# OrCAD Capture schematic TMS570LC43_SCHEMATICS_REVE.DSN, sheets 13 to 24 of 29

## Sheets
13 PAGE27: Power Input: size B; note: Power Input
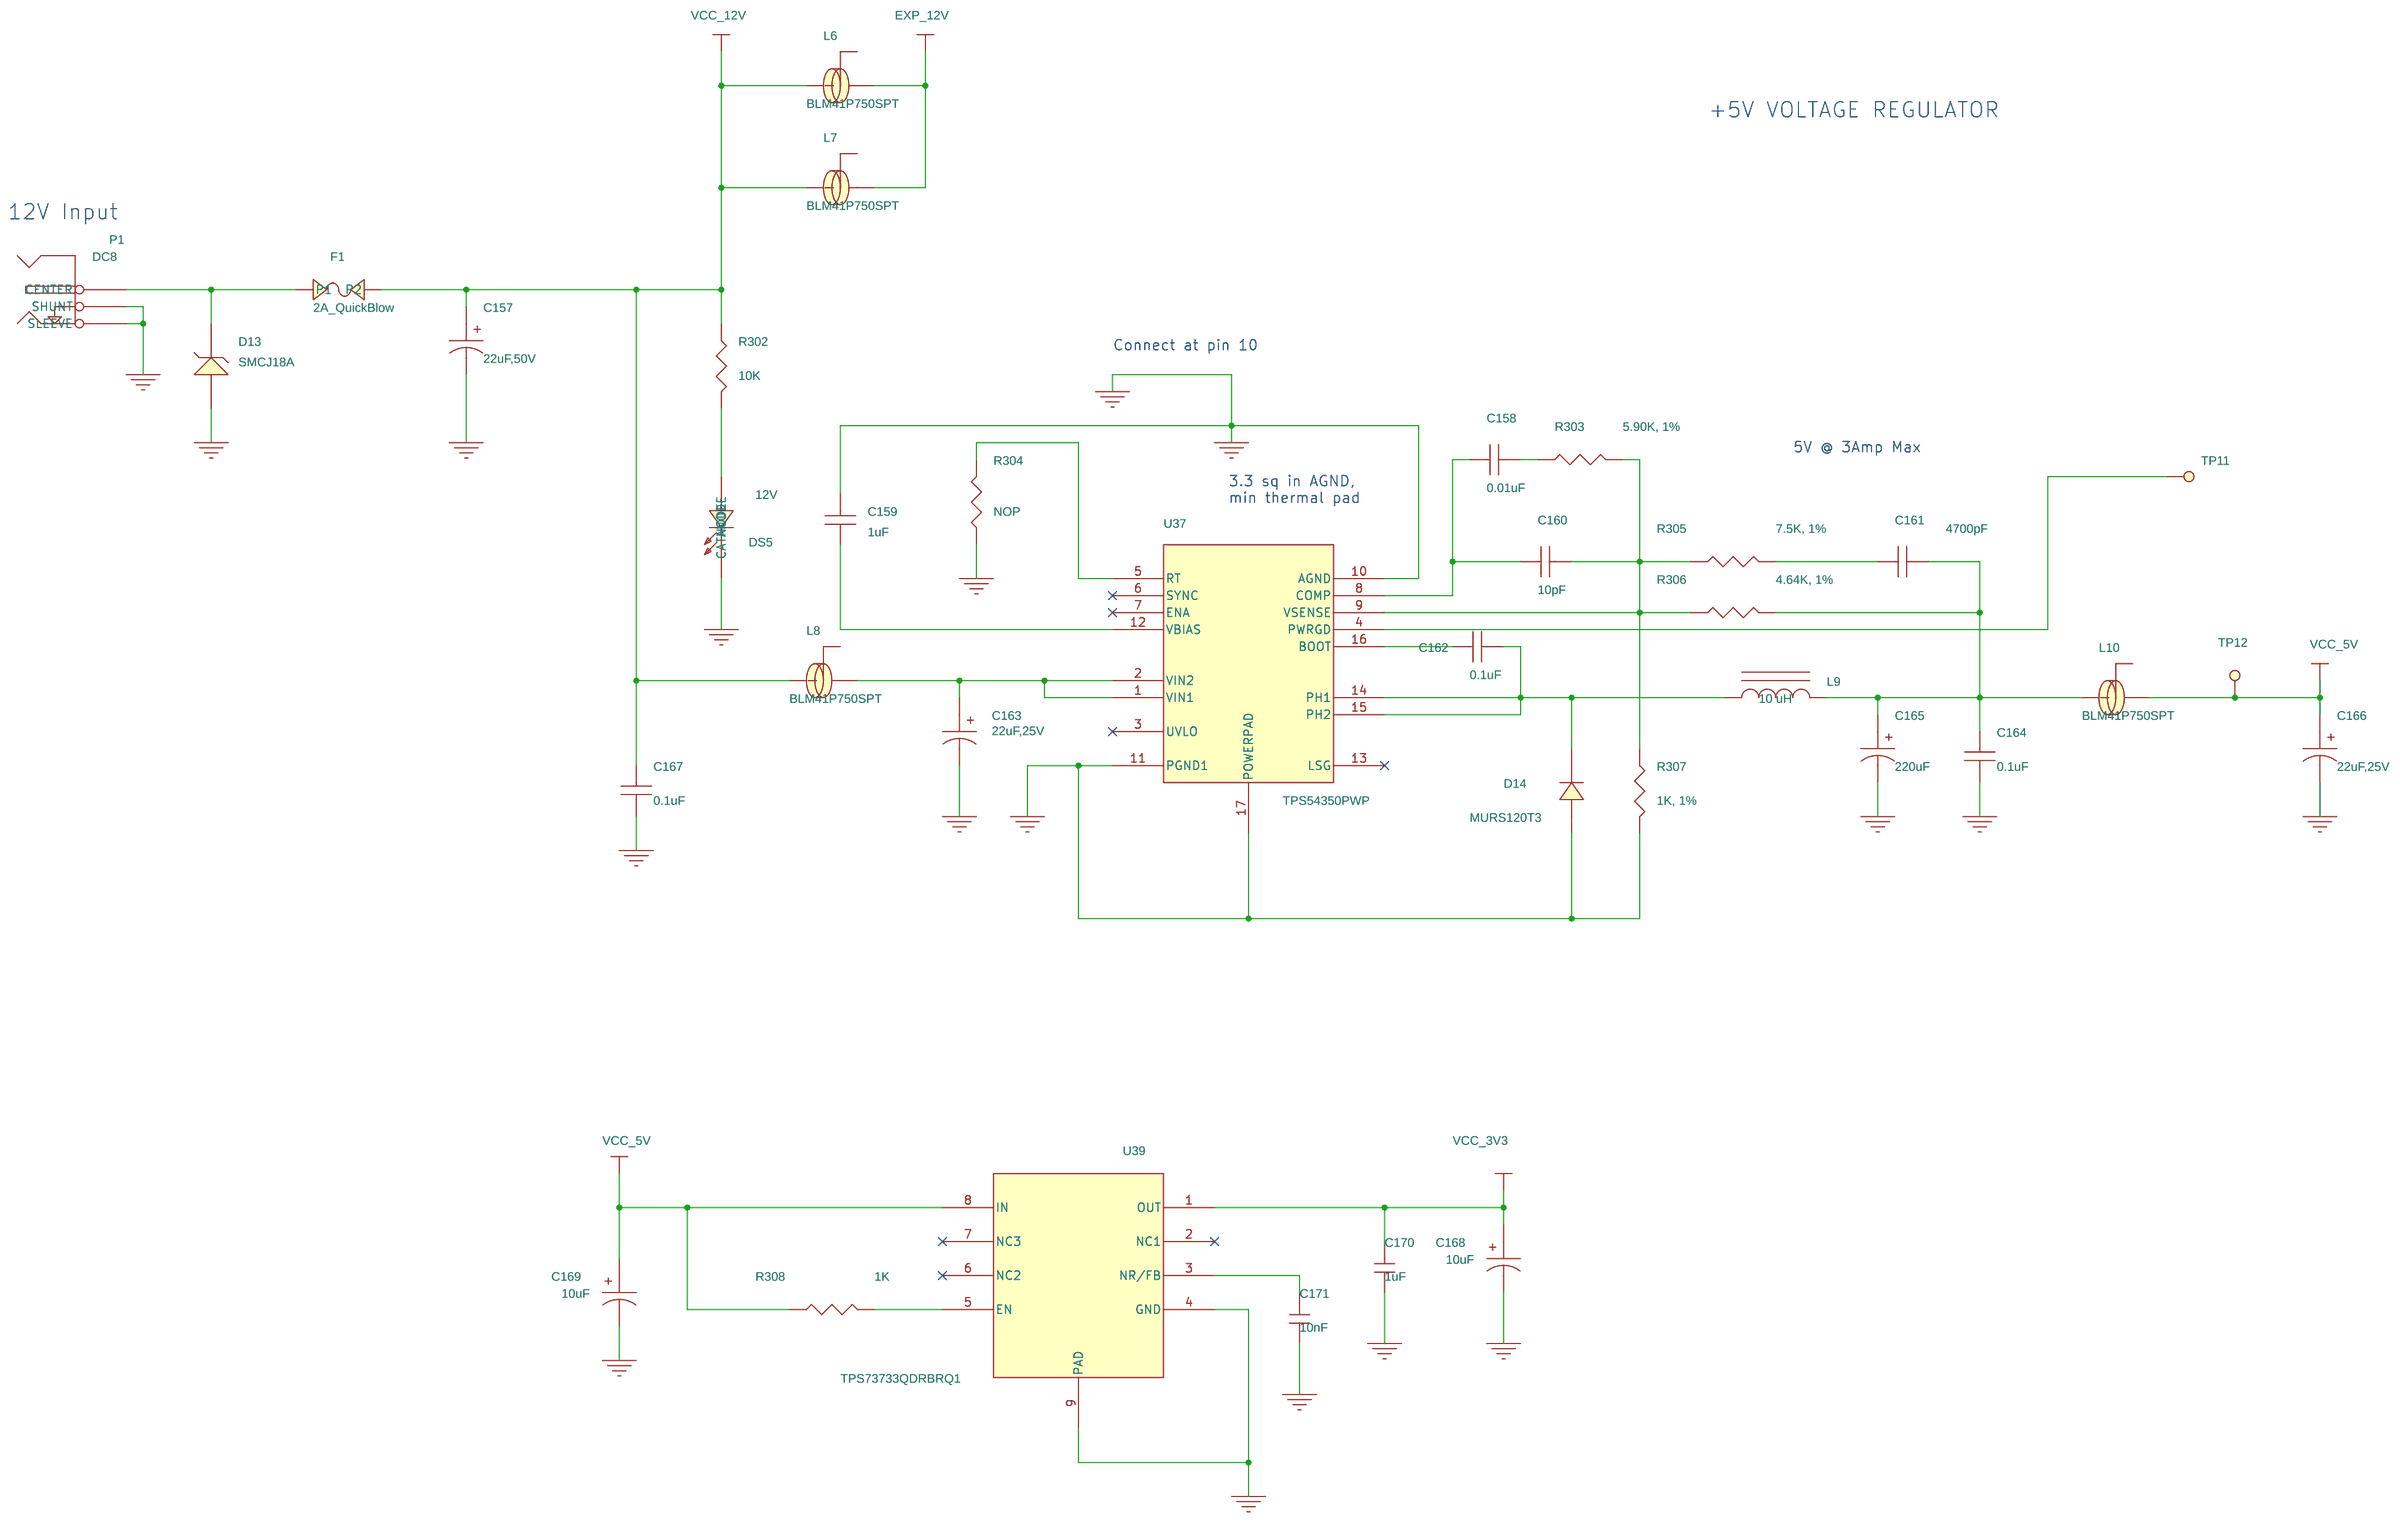
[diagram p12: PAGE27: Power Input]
14 PAGE07: MCU JTAG & OSC: size B; rev: D; note: MCU JTAG & OSC
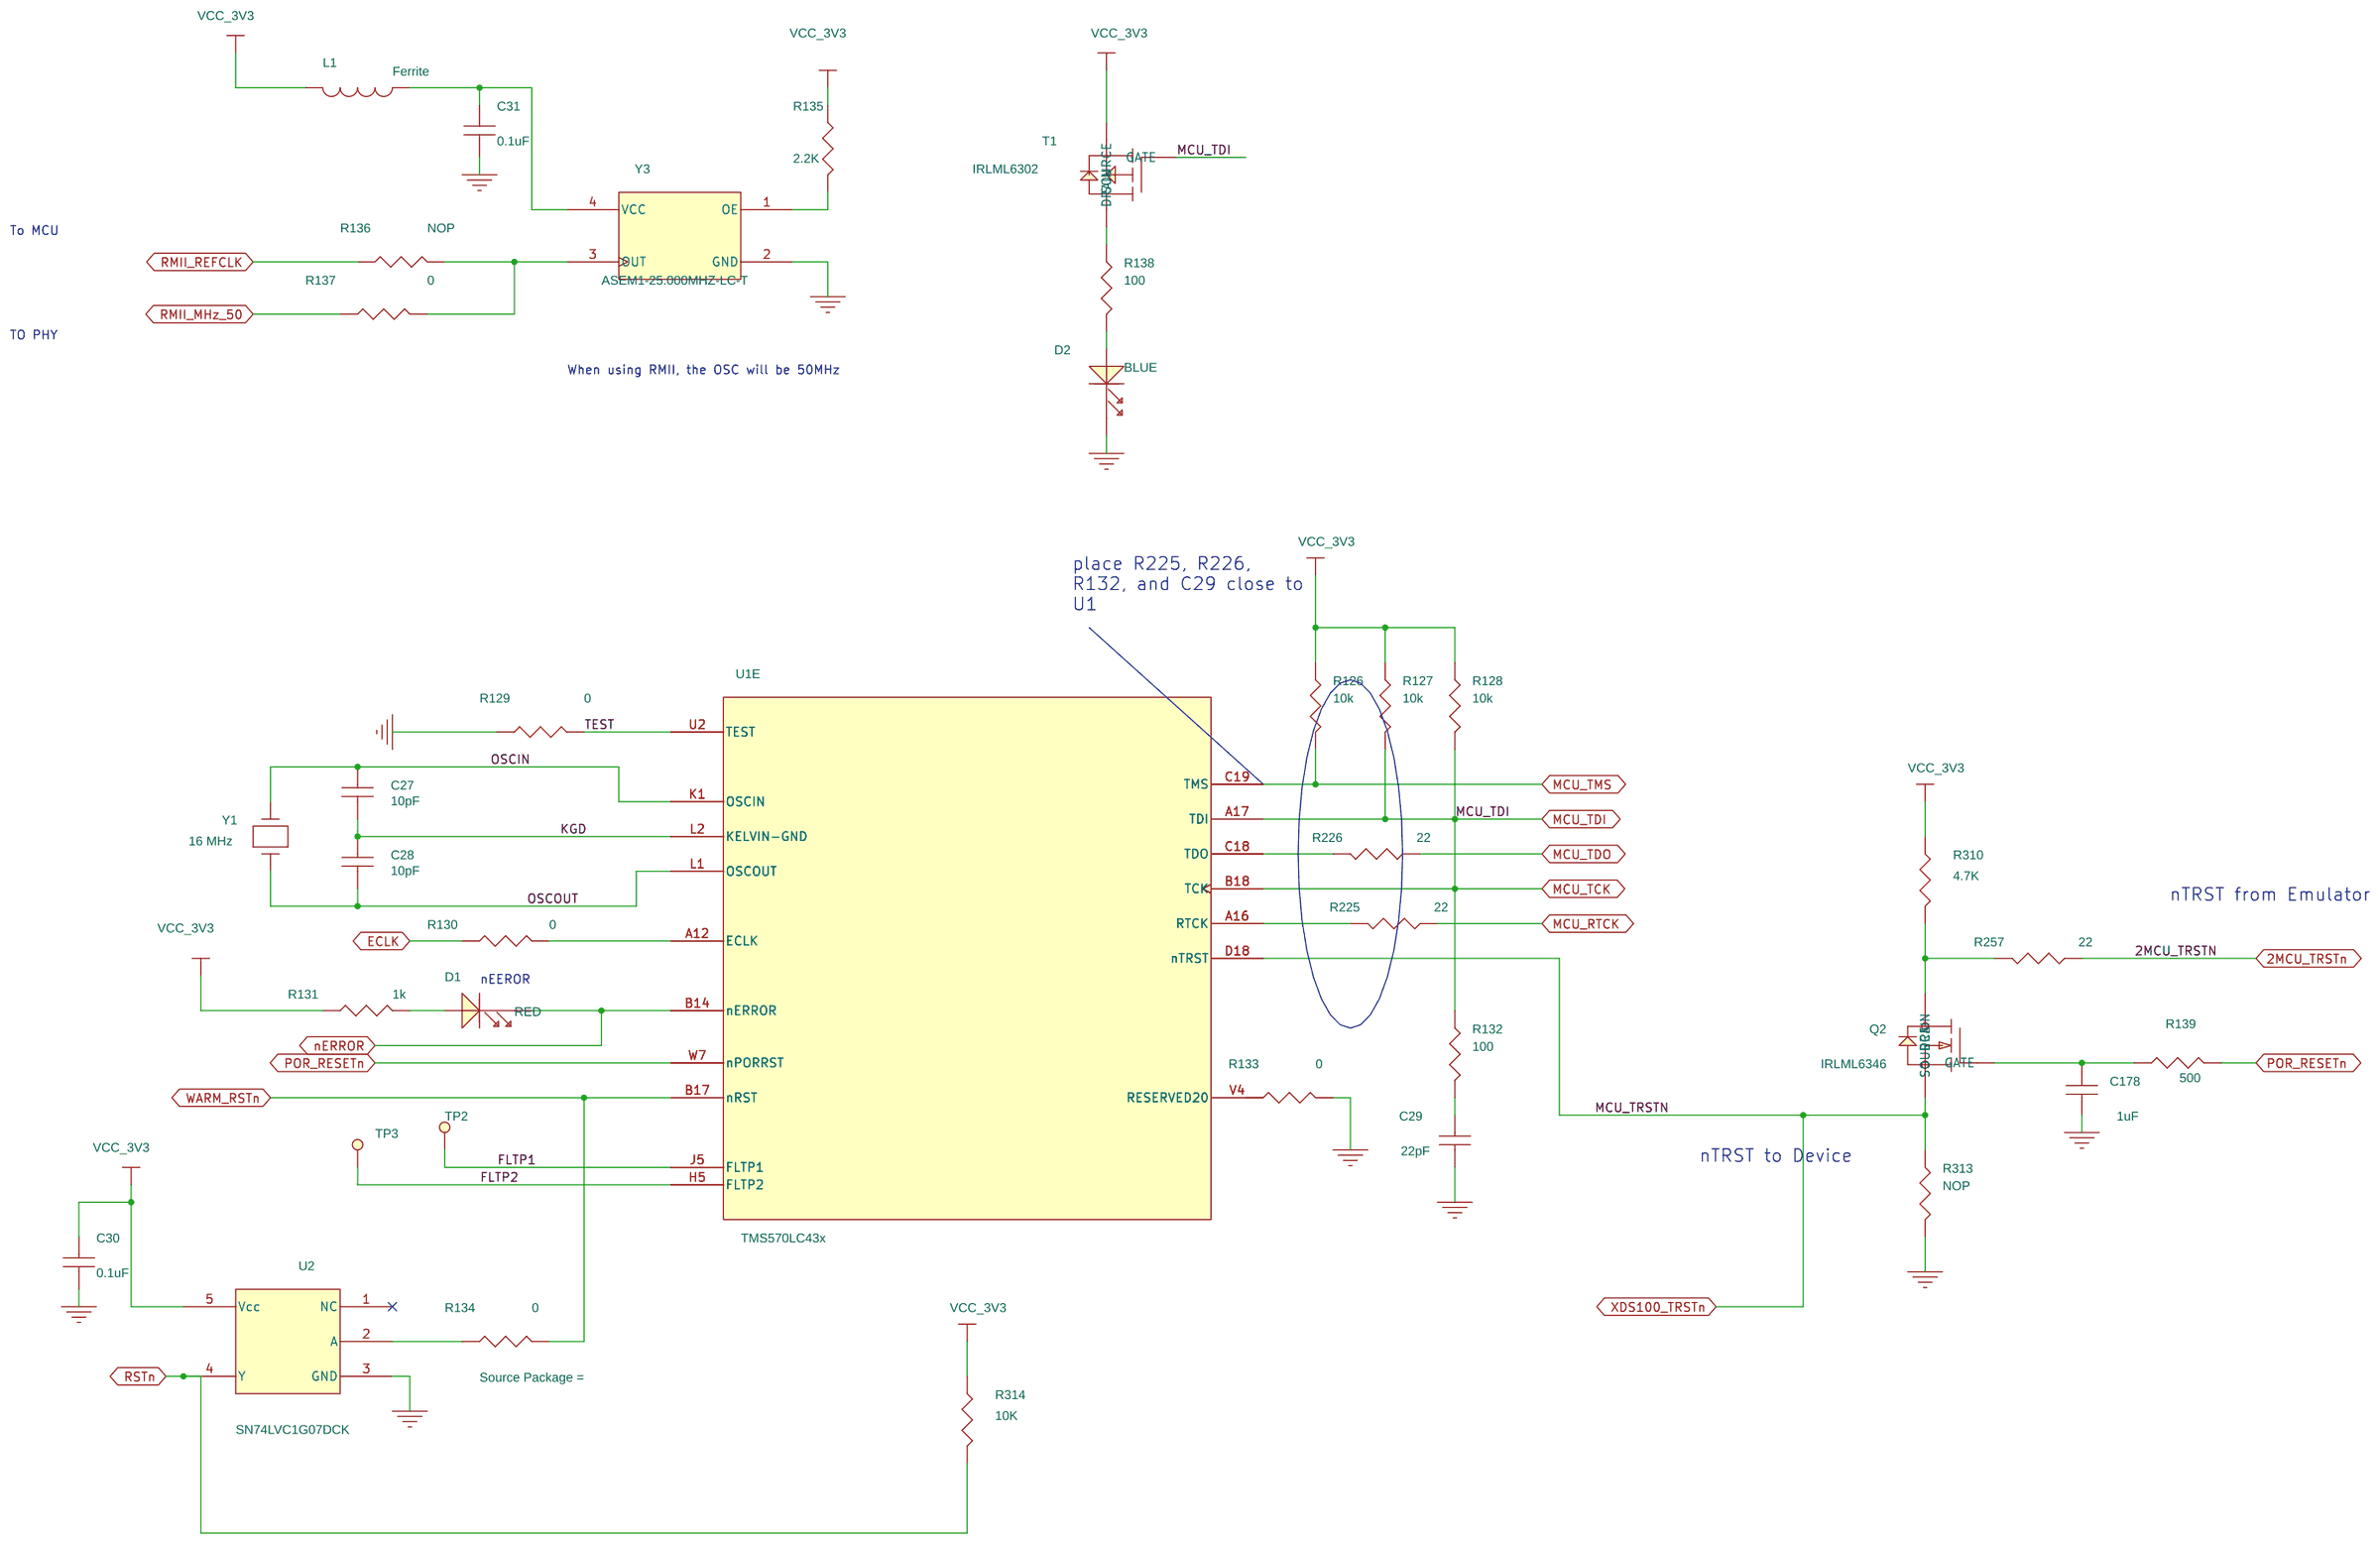
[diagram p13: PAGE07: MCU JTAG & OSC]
15 PAGE24: XDS100V2 CPLD: size B; note: XDS100V2 CPLD
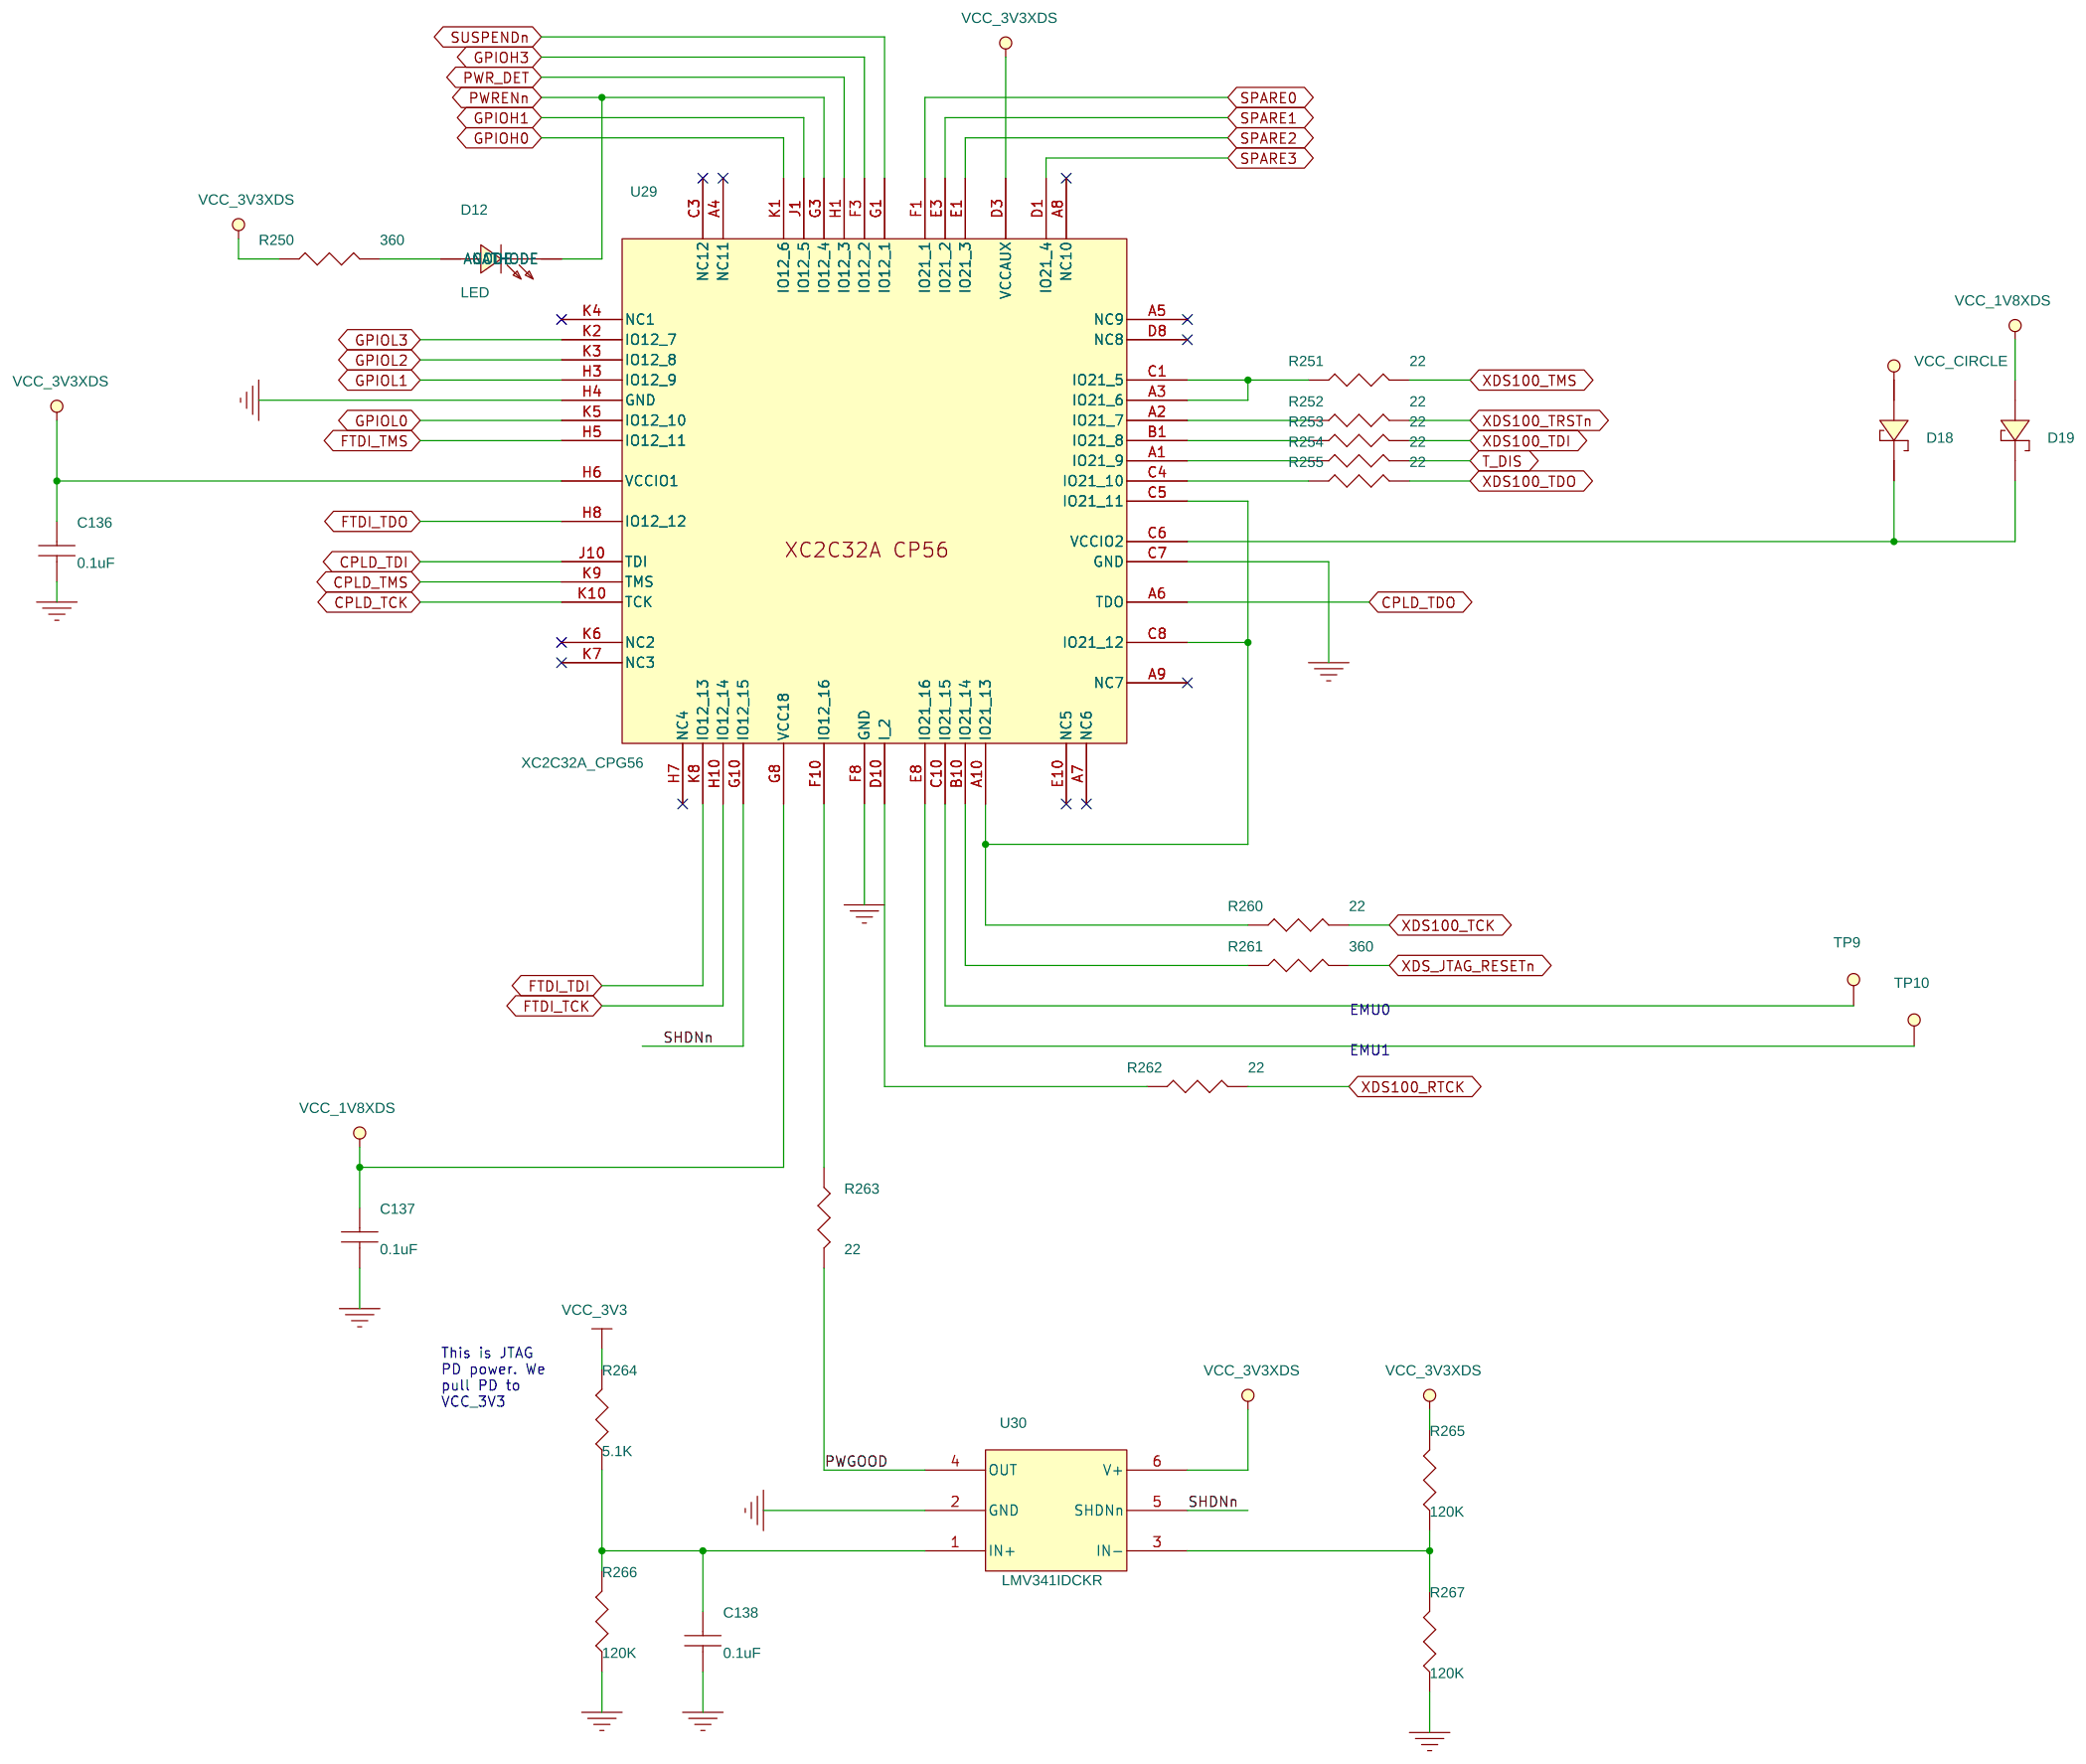
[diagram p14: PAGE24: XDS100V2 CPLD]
16 PAGE10: MCU Power & GND: size B; note: MCU Power & GND
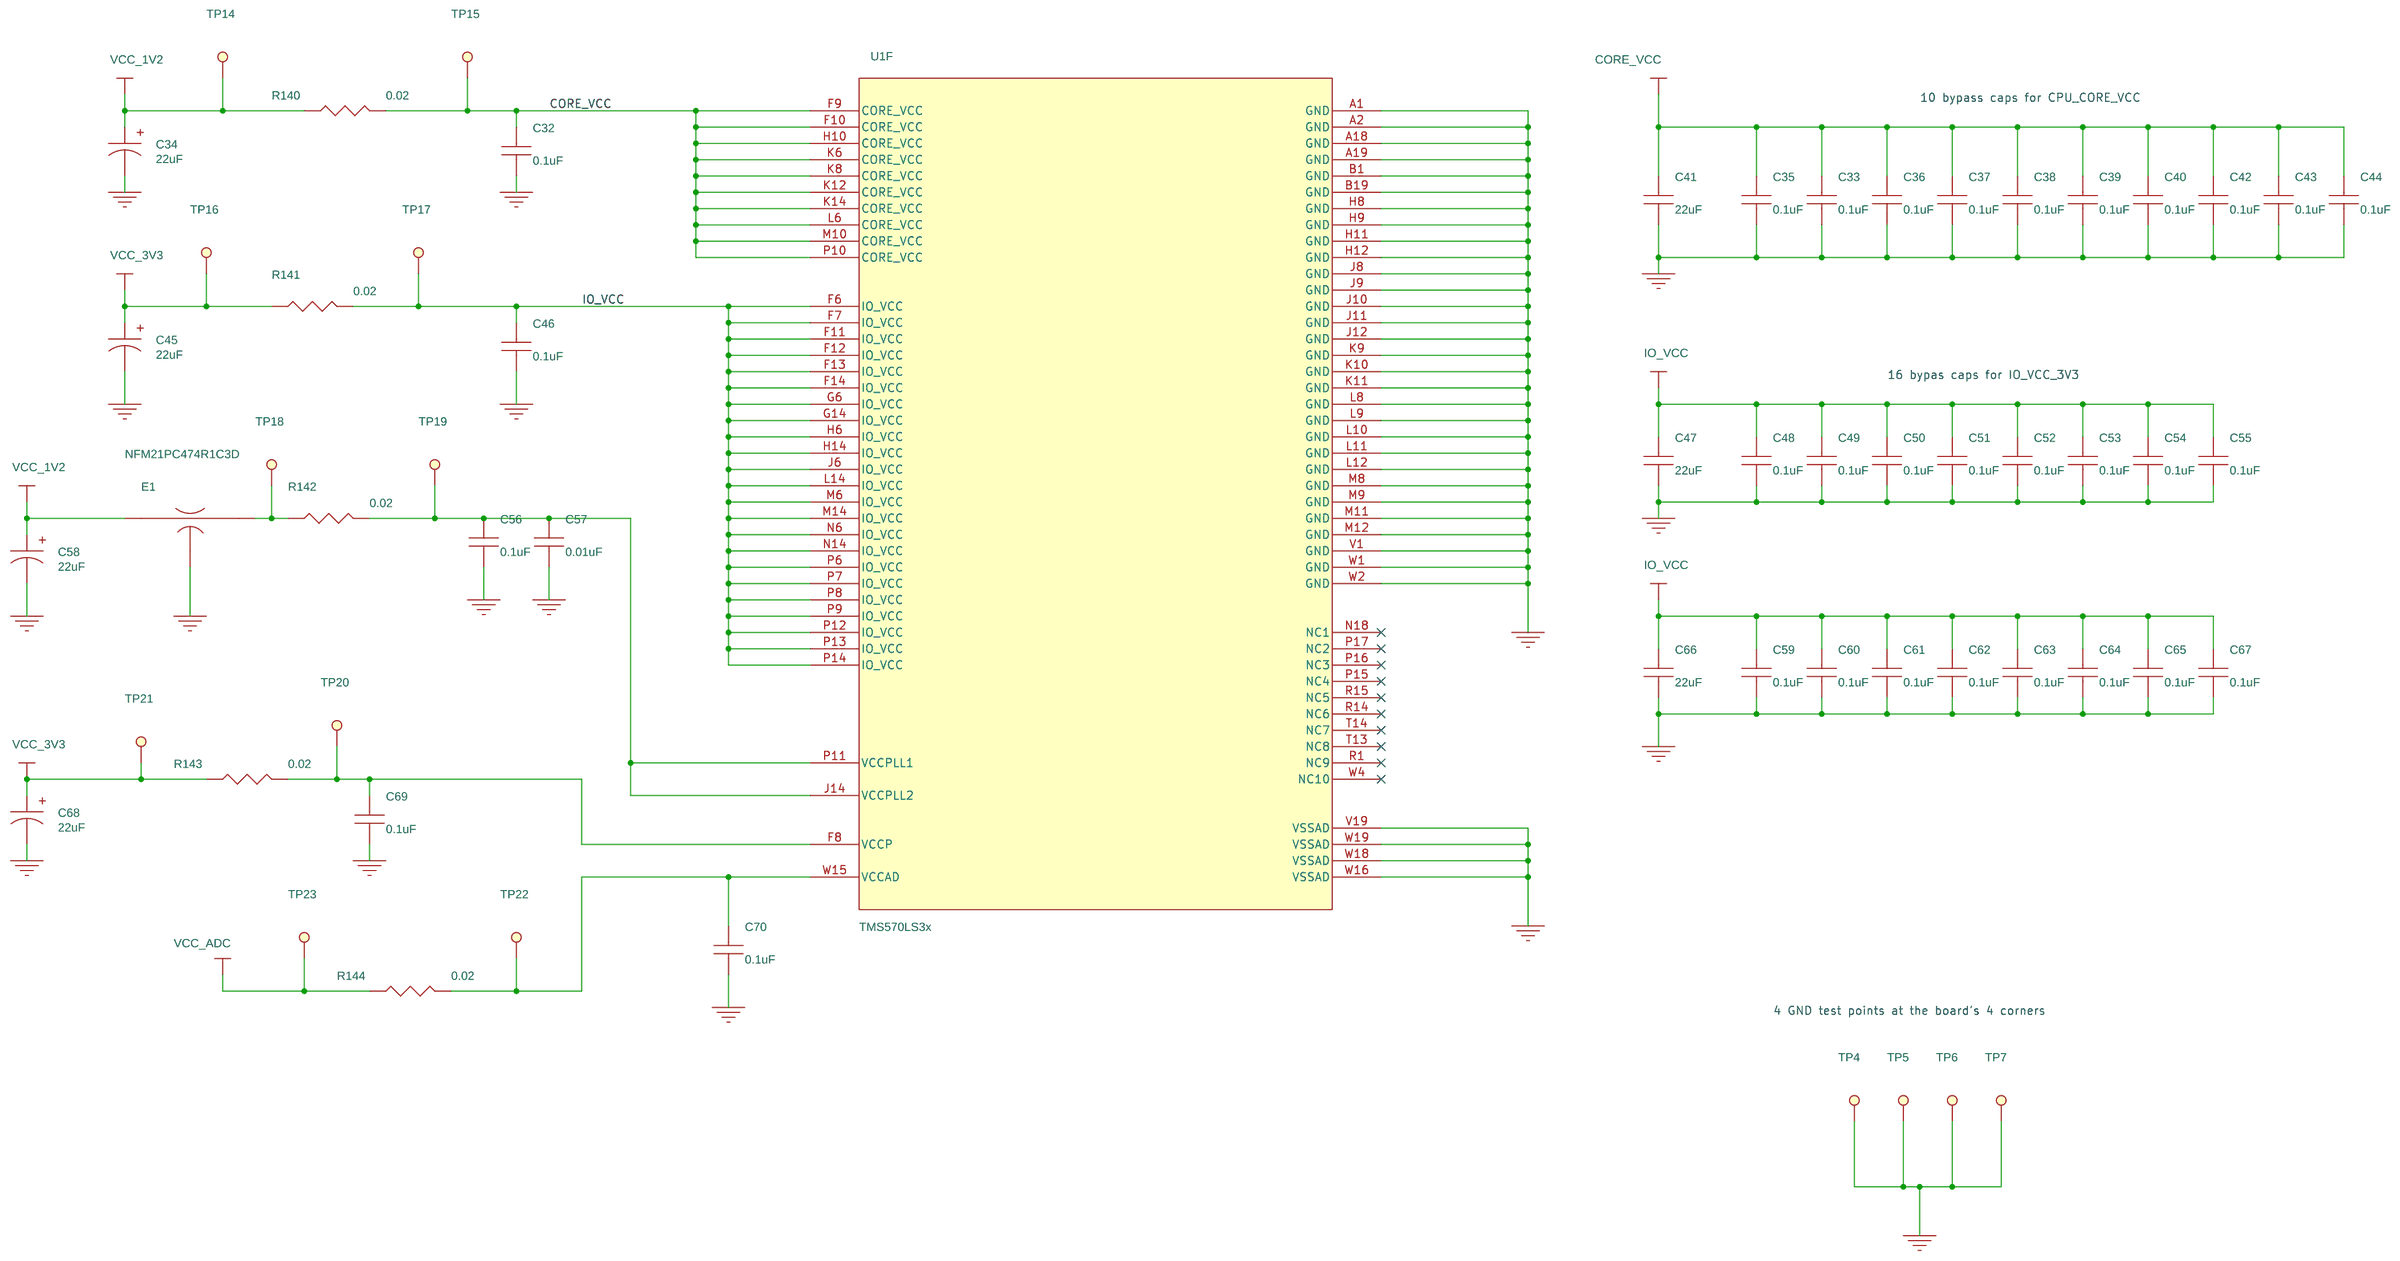
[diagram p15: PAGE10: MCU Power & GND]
17 PAGE16: USB 1st OHCI Host: size B; note: USB 1st OHCI Host
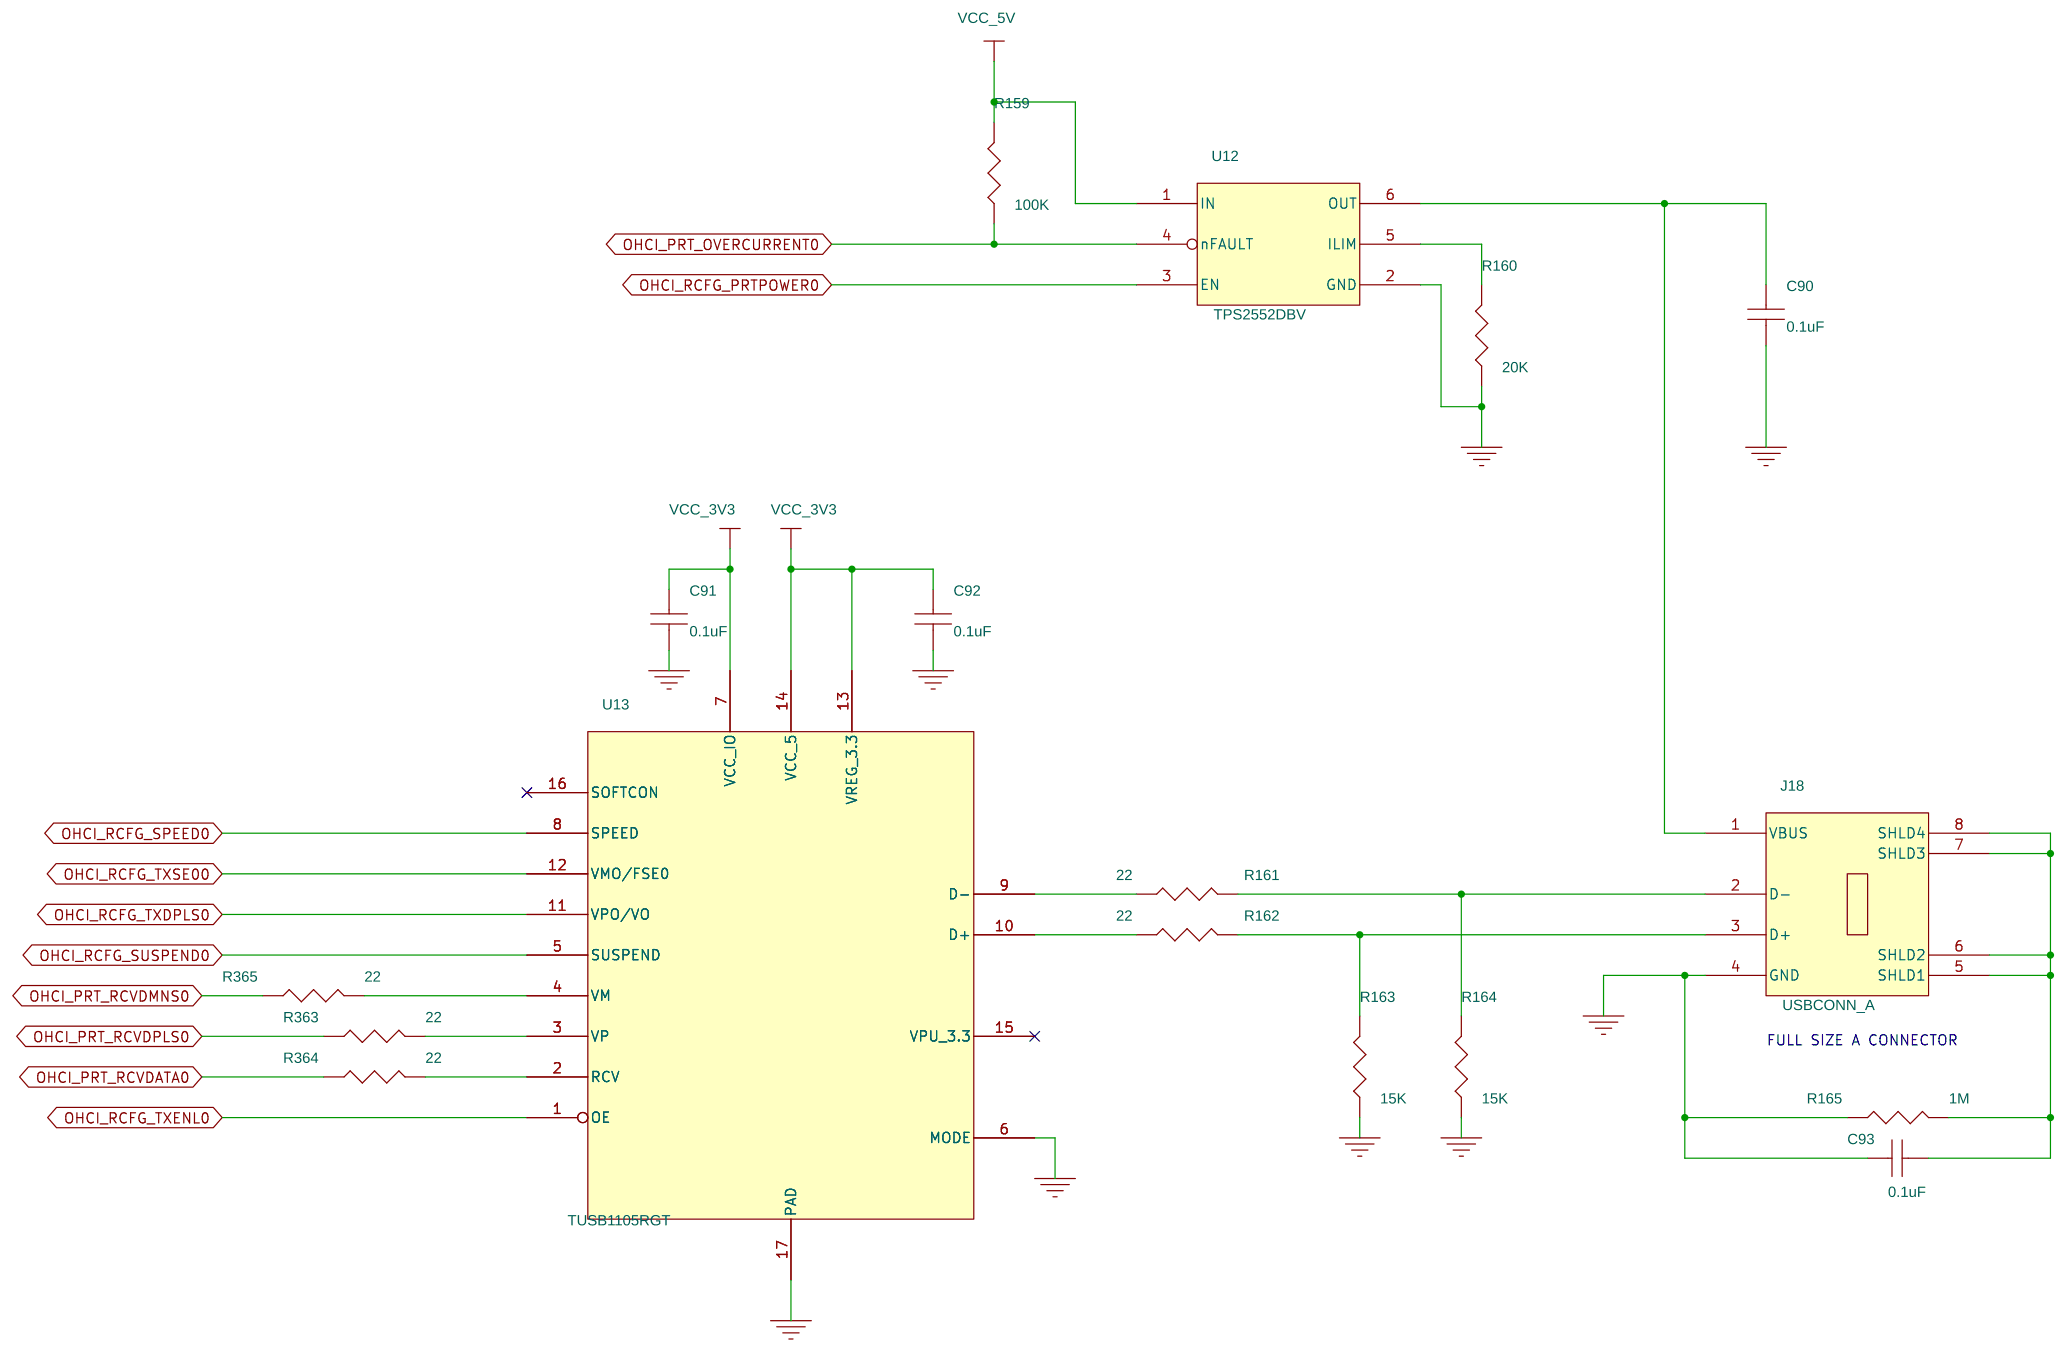
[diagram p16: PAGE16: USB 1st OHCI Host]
18 PAGE21: JTAG & MIPI Conn: size B; note: JTAG & MIPI Connectors
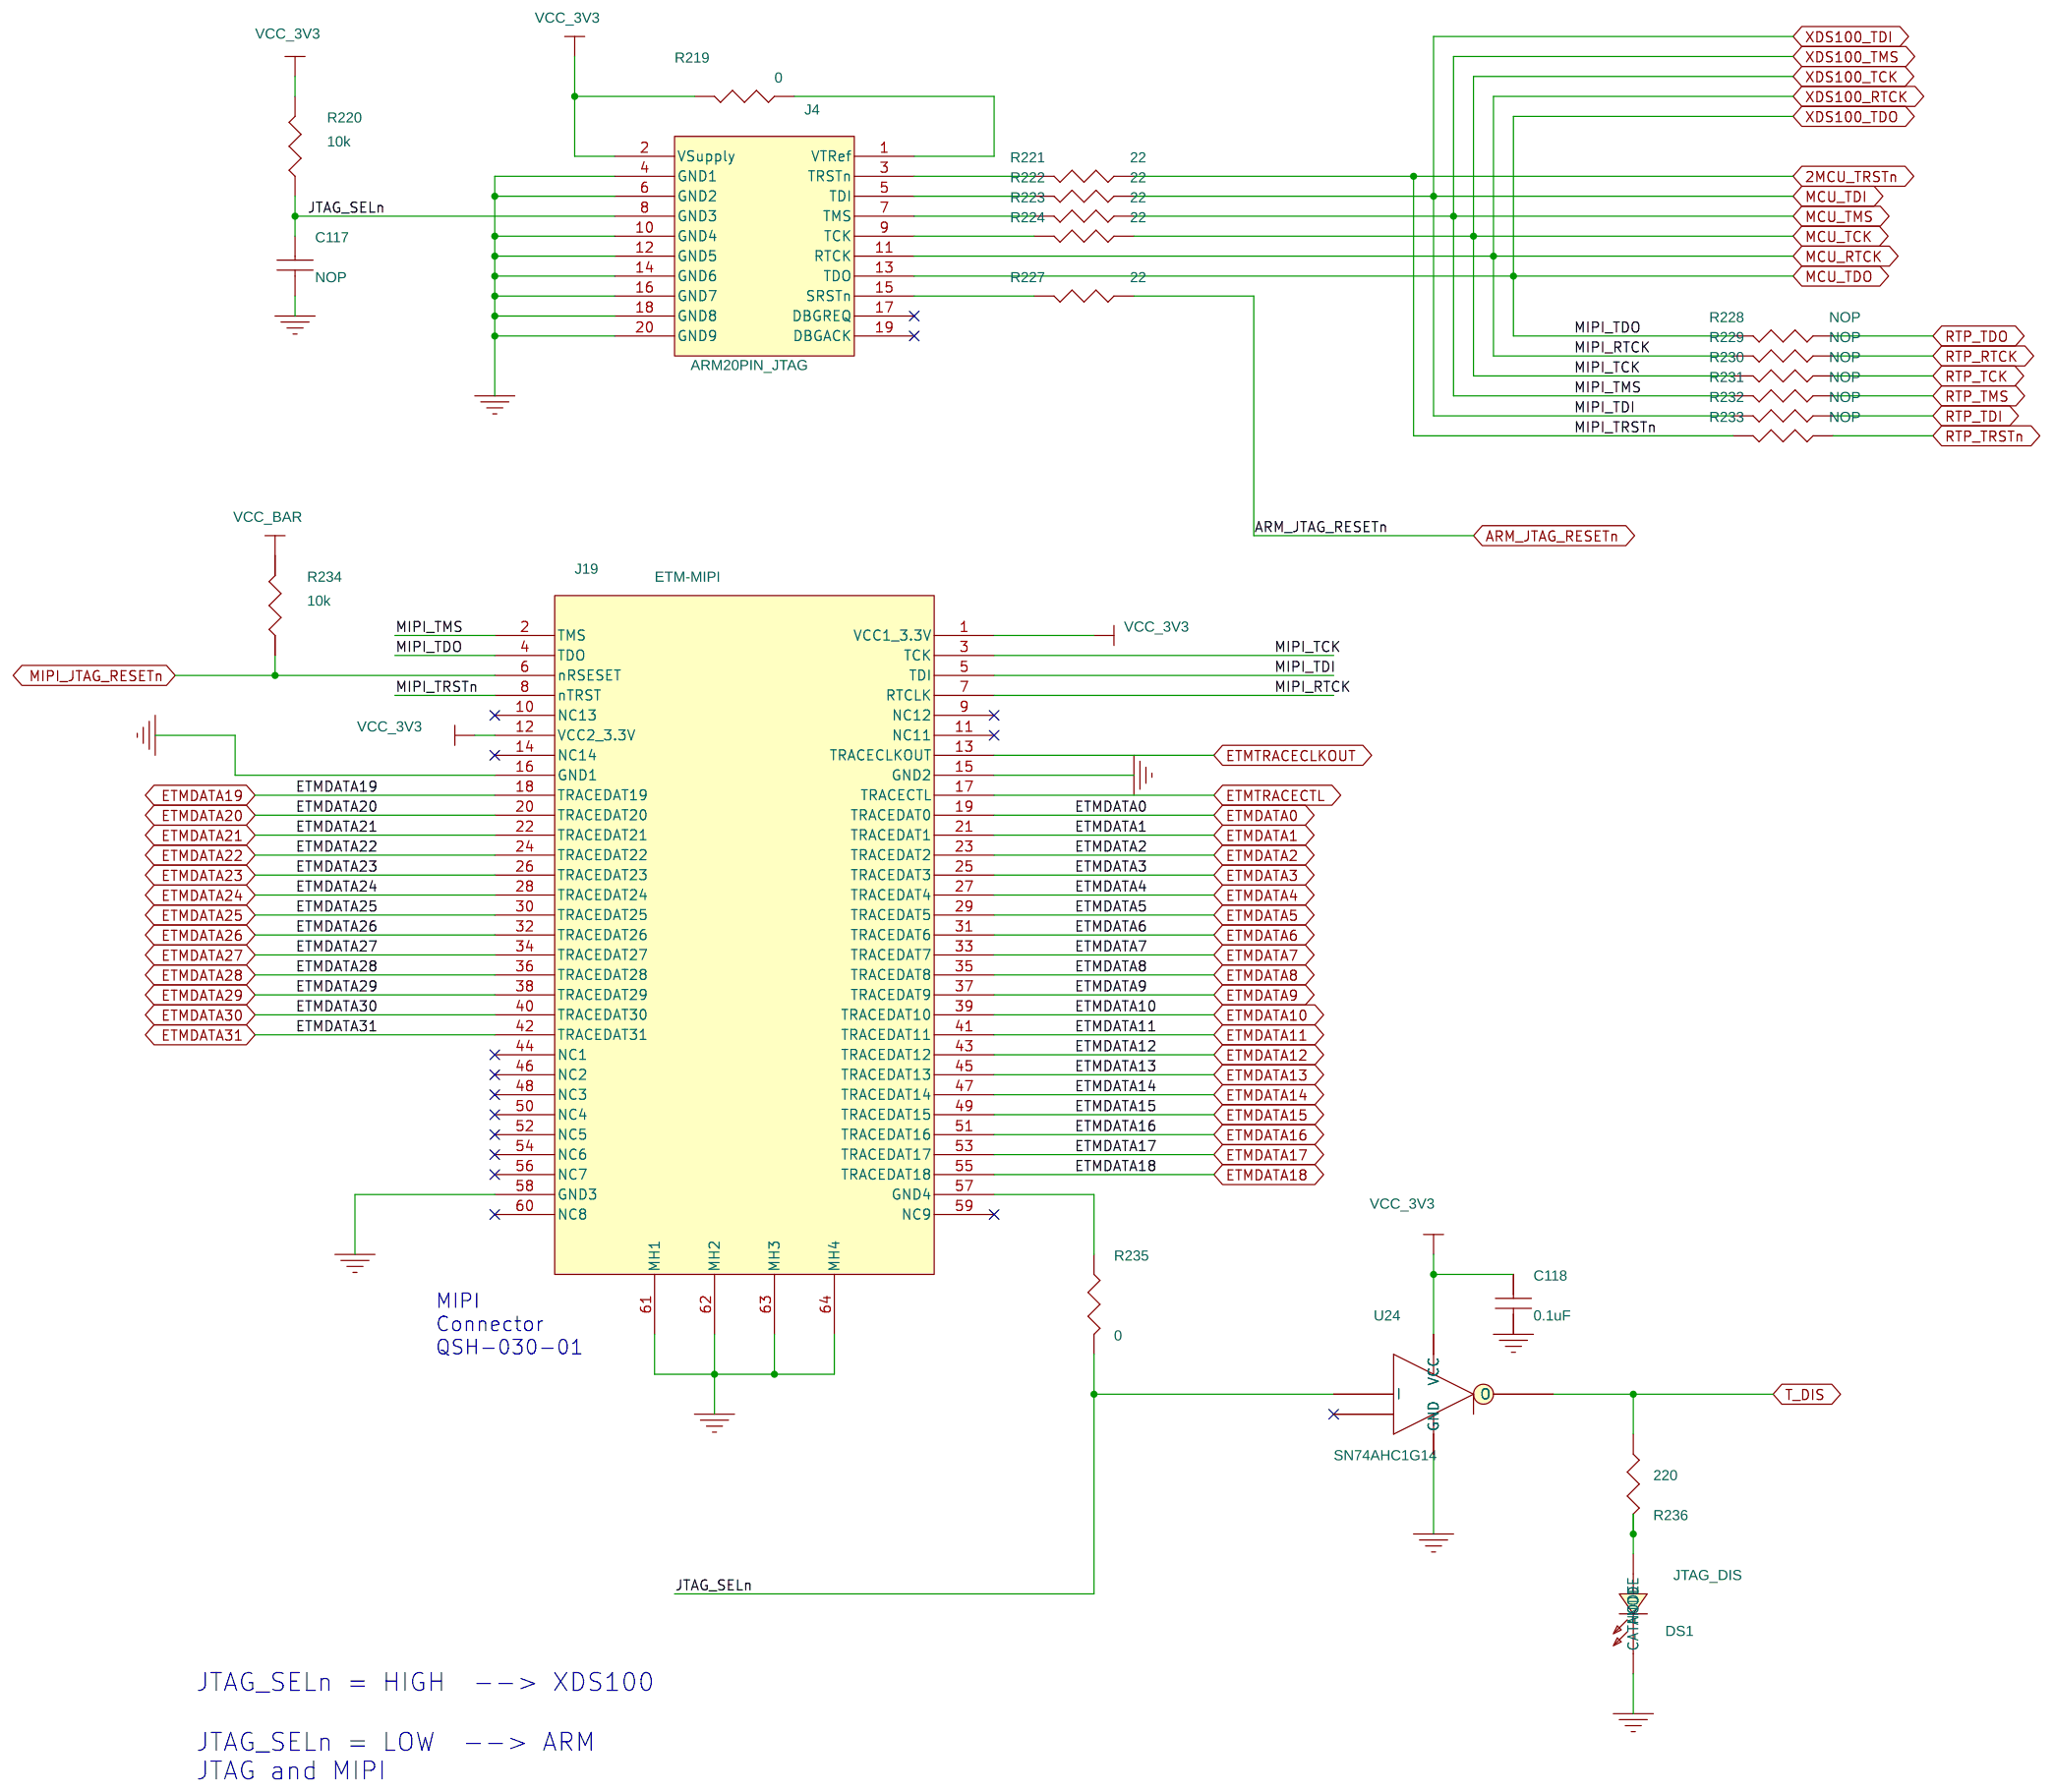
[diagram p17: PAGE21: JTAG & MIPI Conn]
19 PAGE20: CAN Transceivers: size B; note: DCAN Transceivers
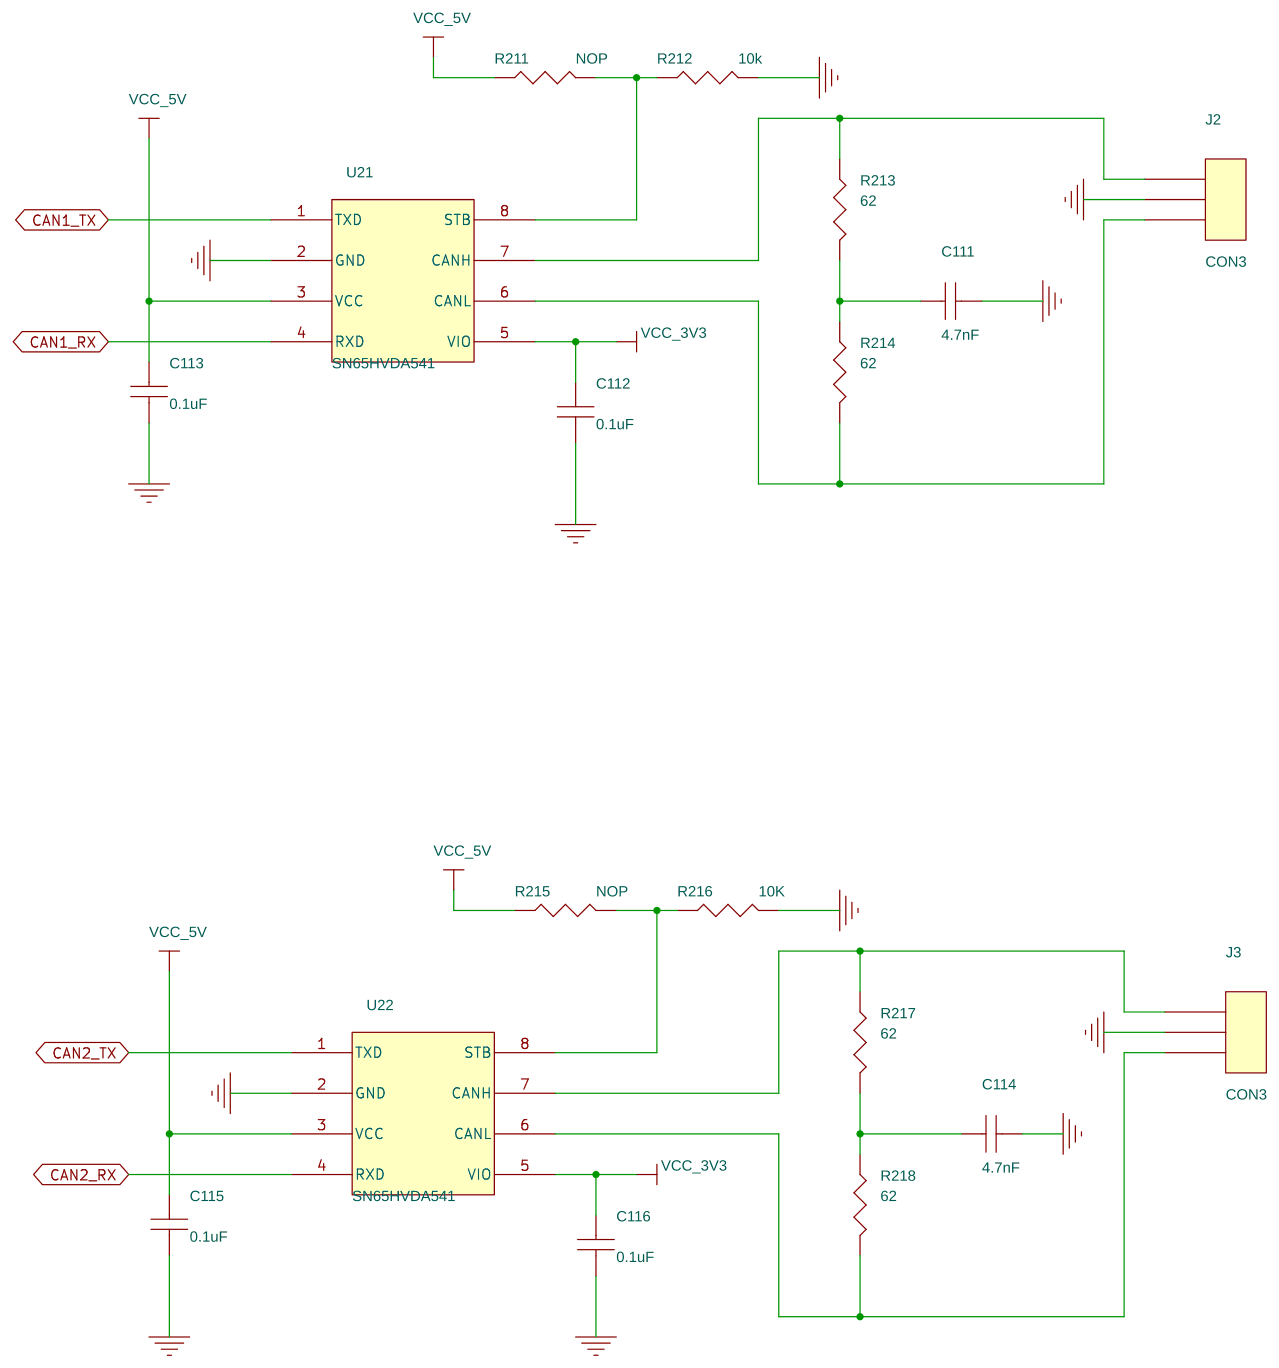
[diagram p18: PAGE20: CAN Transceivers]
20 PAGE12: EMIF ADDR/ETM/RTP: size B; note: EMIF DATA and ADDR BUSES
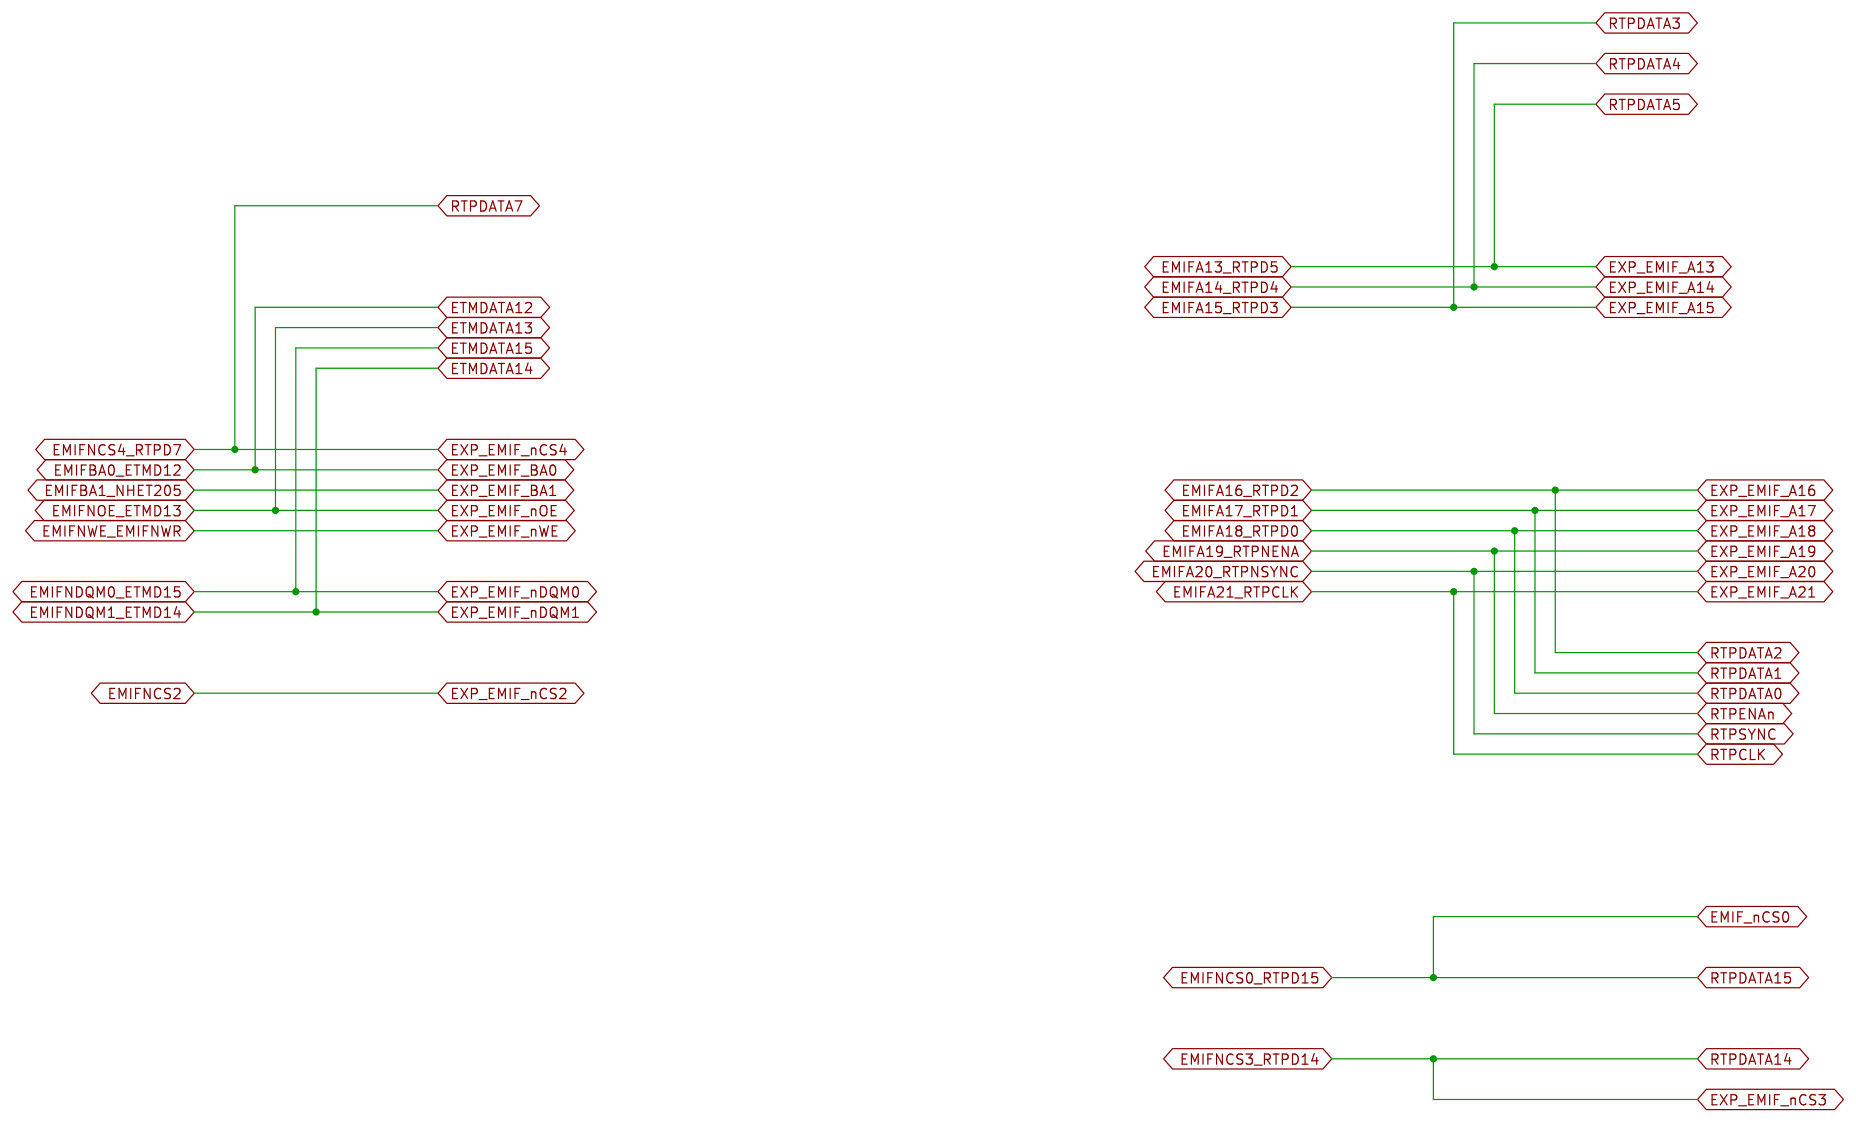
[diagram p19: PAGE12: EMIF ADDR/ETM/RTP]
21 PAGE05: MCU ETM & RSVED_RTP: size B; note: MCU ETM & Rsved RTP
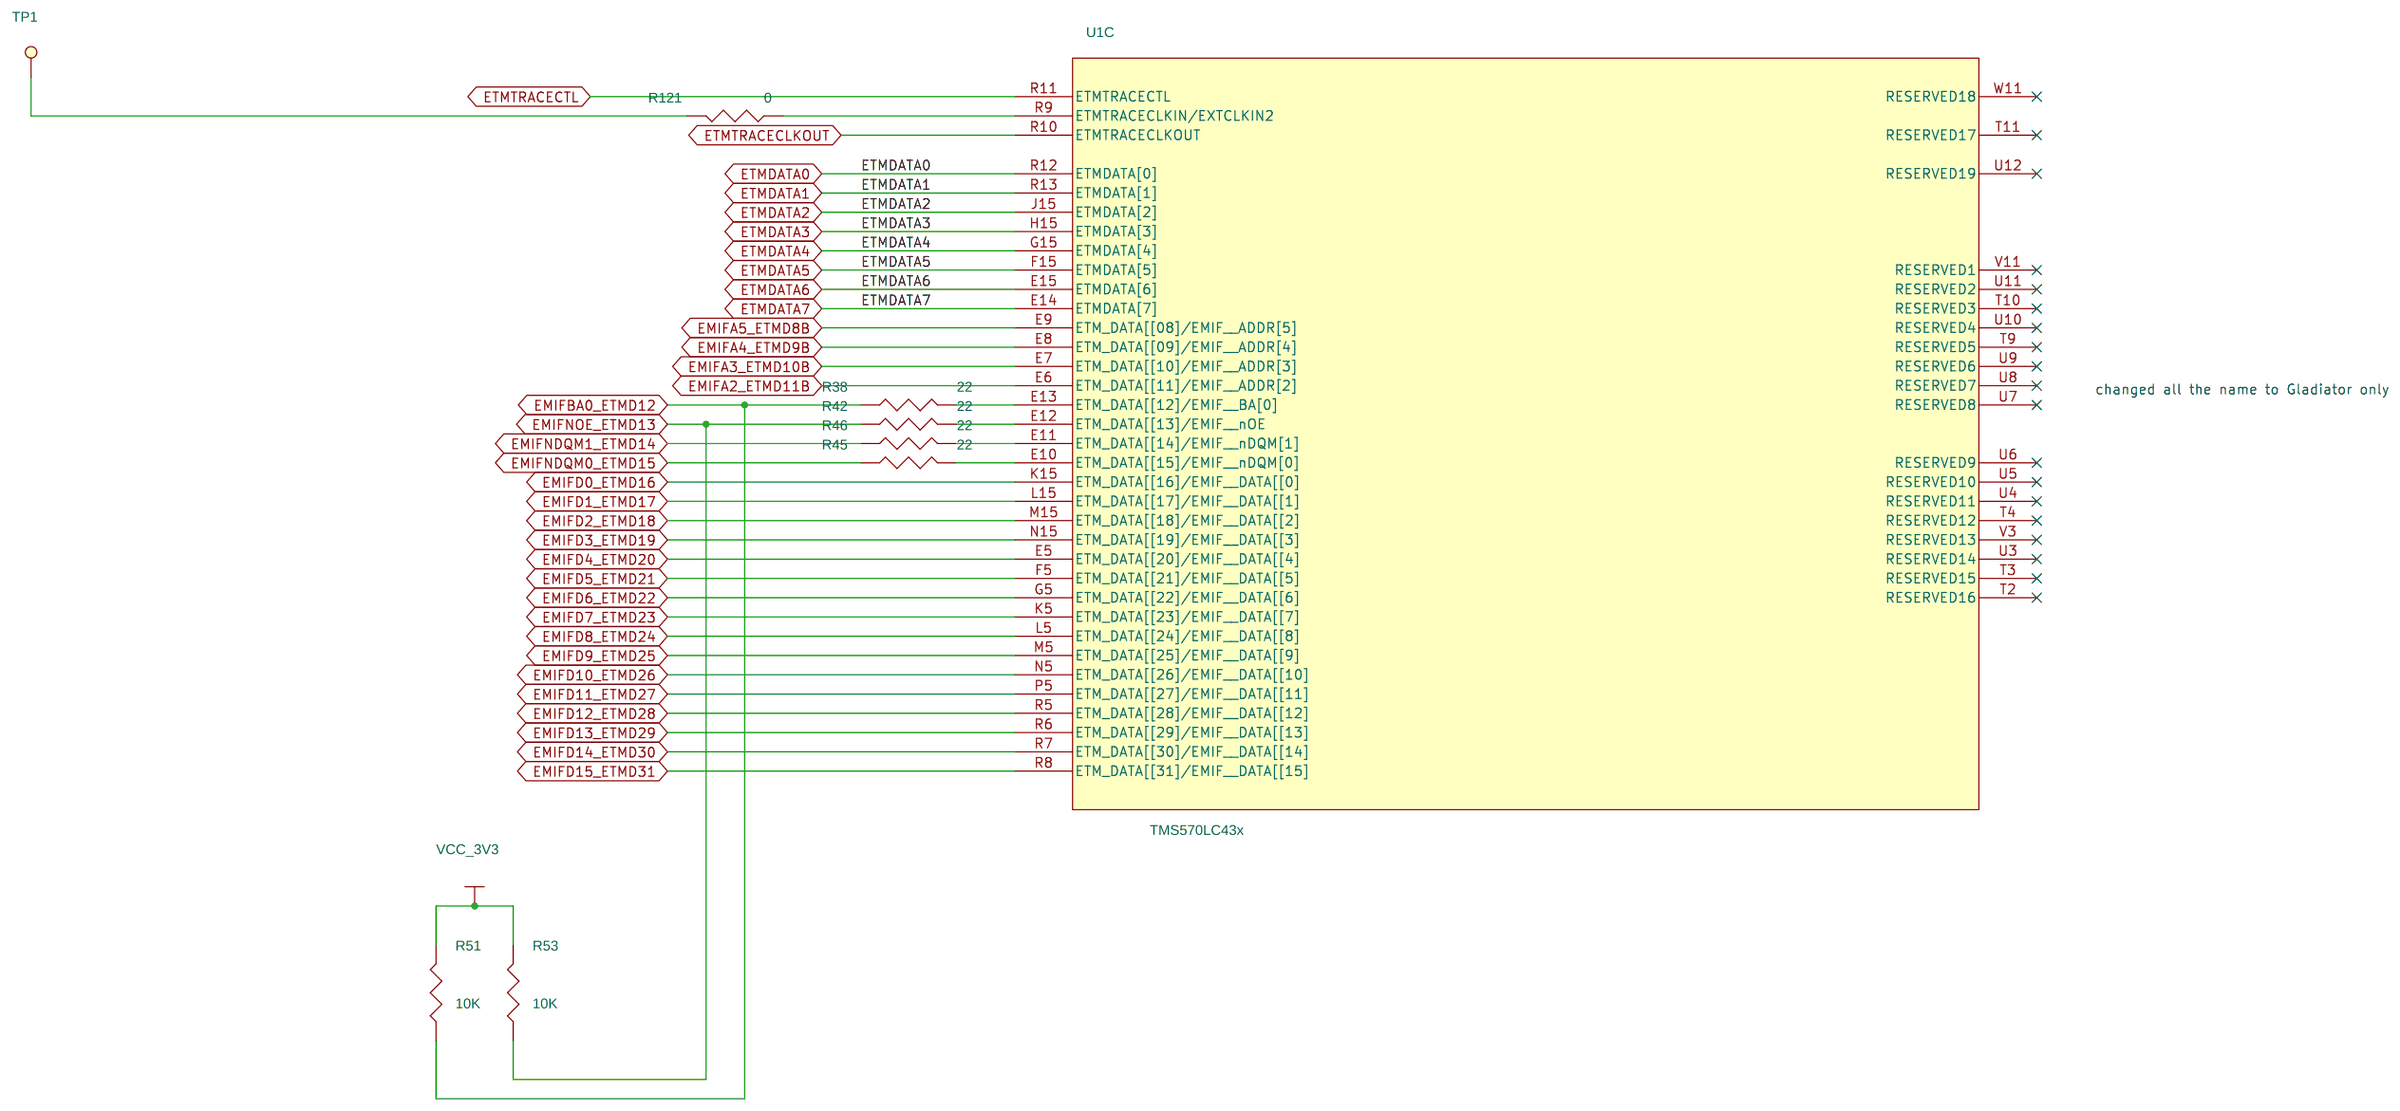
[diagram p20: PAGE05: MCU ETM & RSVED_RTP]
22 PAGE28: EXP P1 and EXP P2: size B; note: Expansion Connector 1
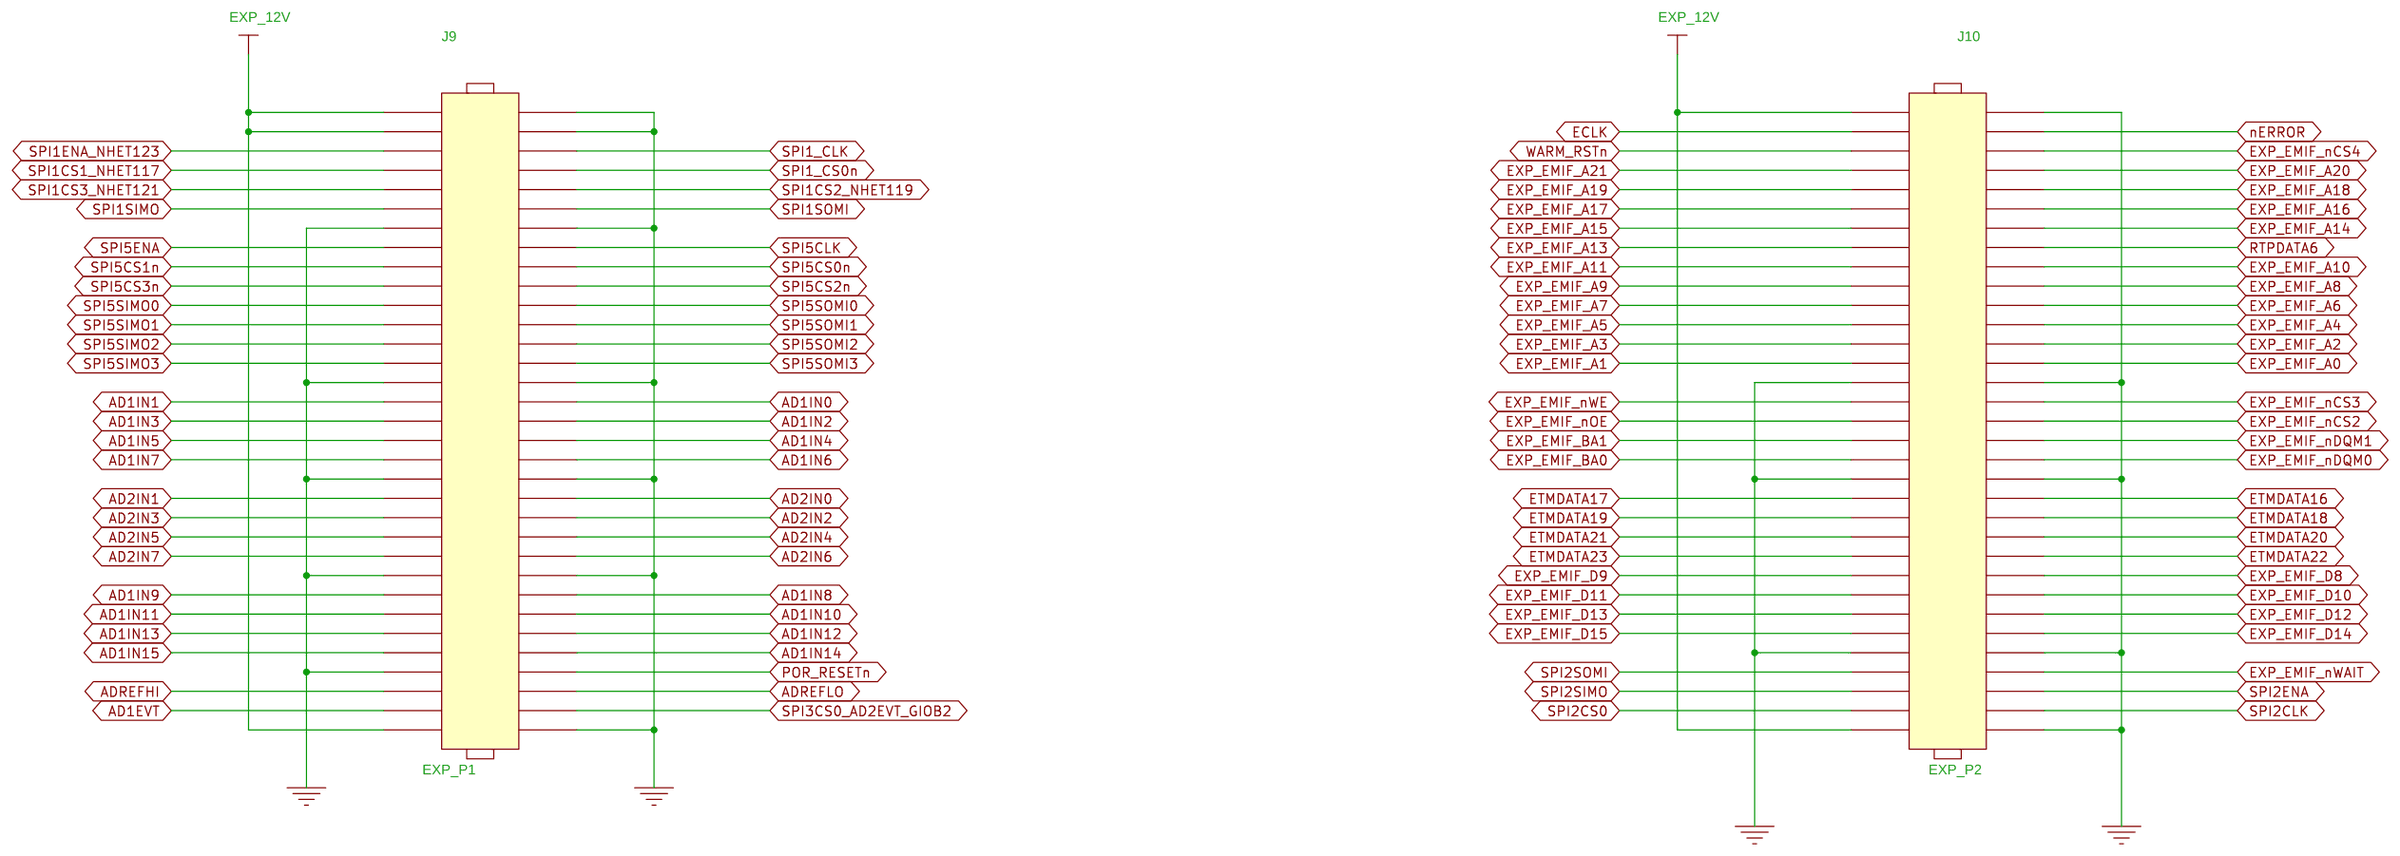
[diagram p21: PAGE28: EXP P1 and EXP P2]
23 PAGE23: XDS100V2 FTDI2232: size B; note: XDS100V2 FTDI2232
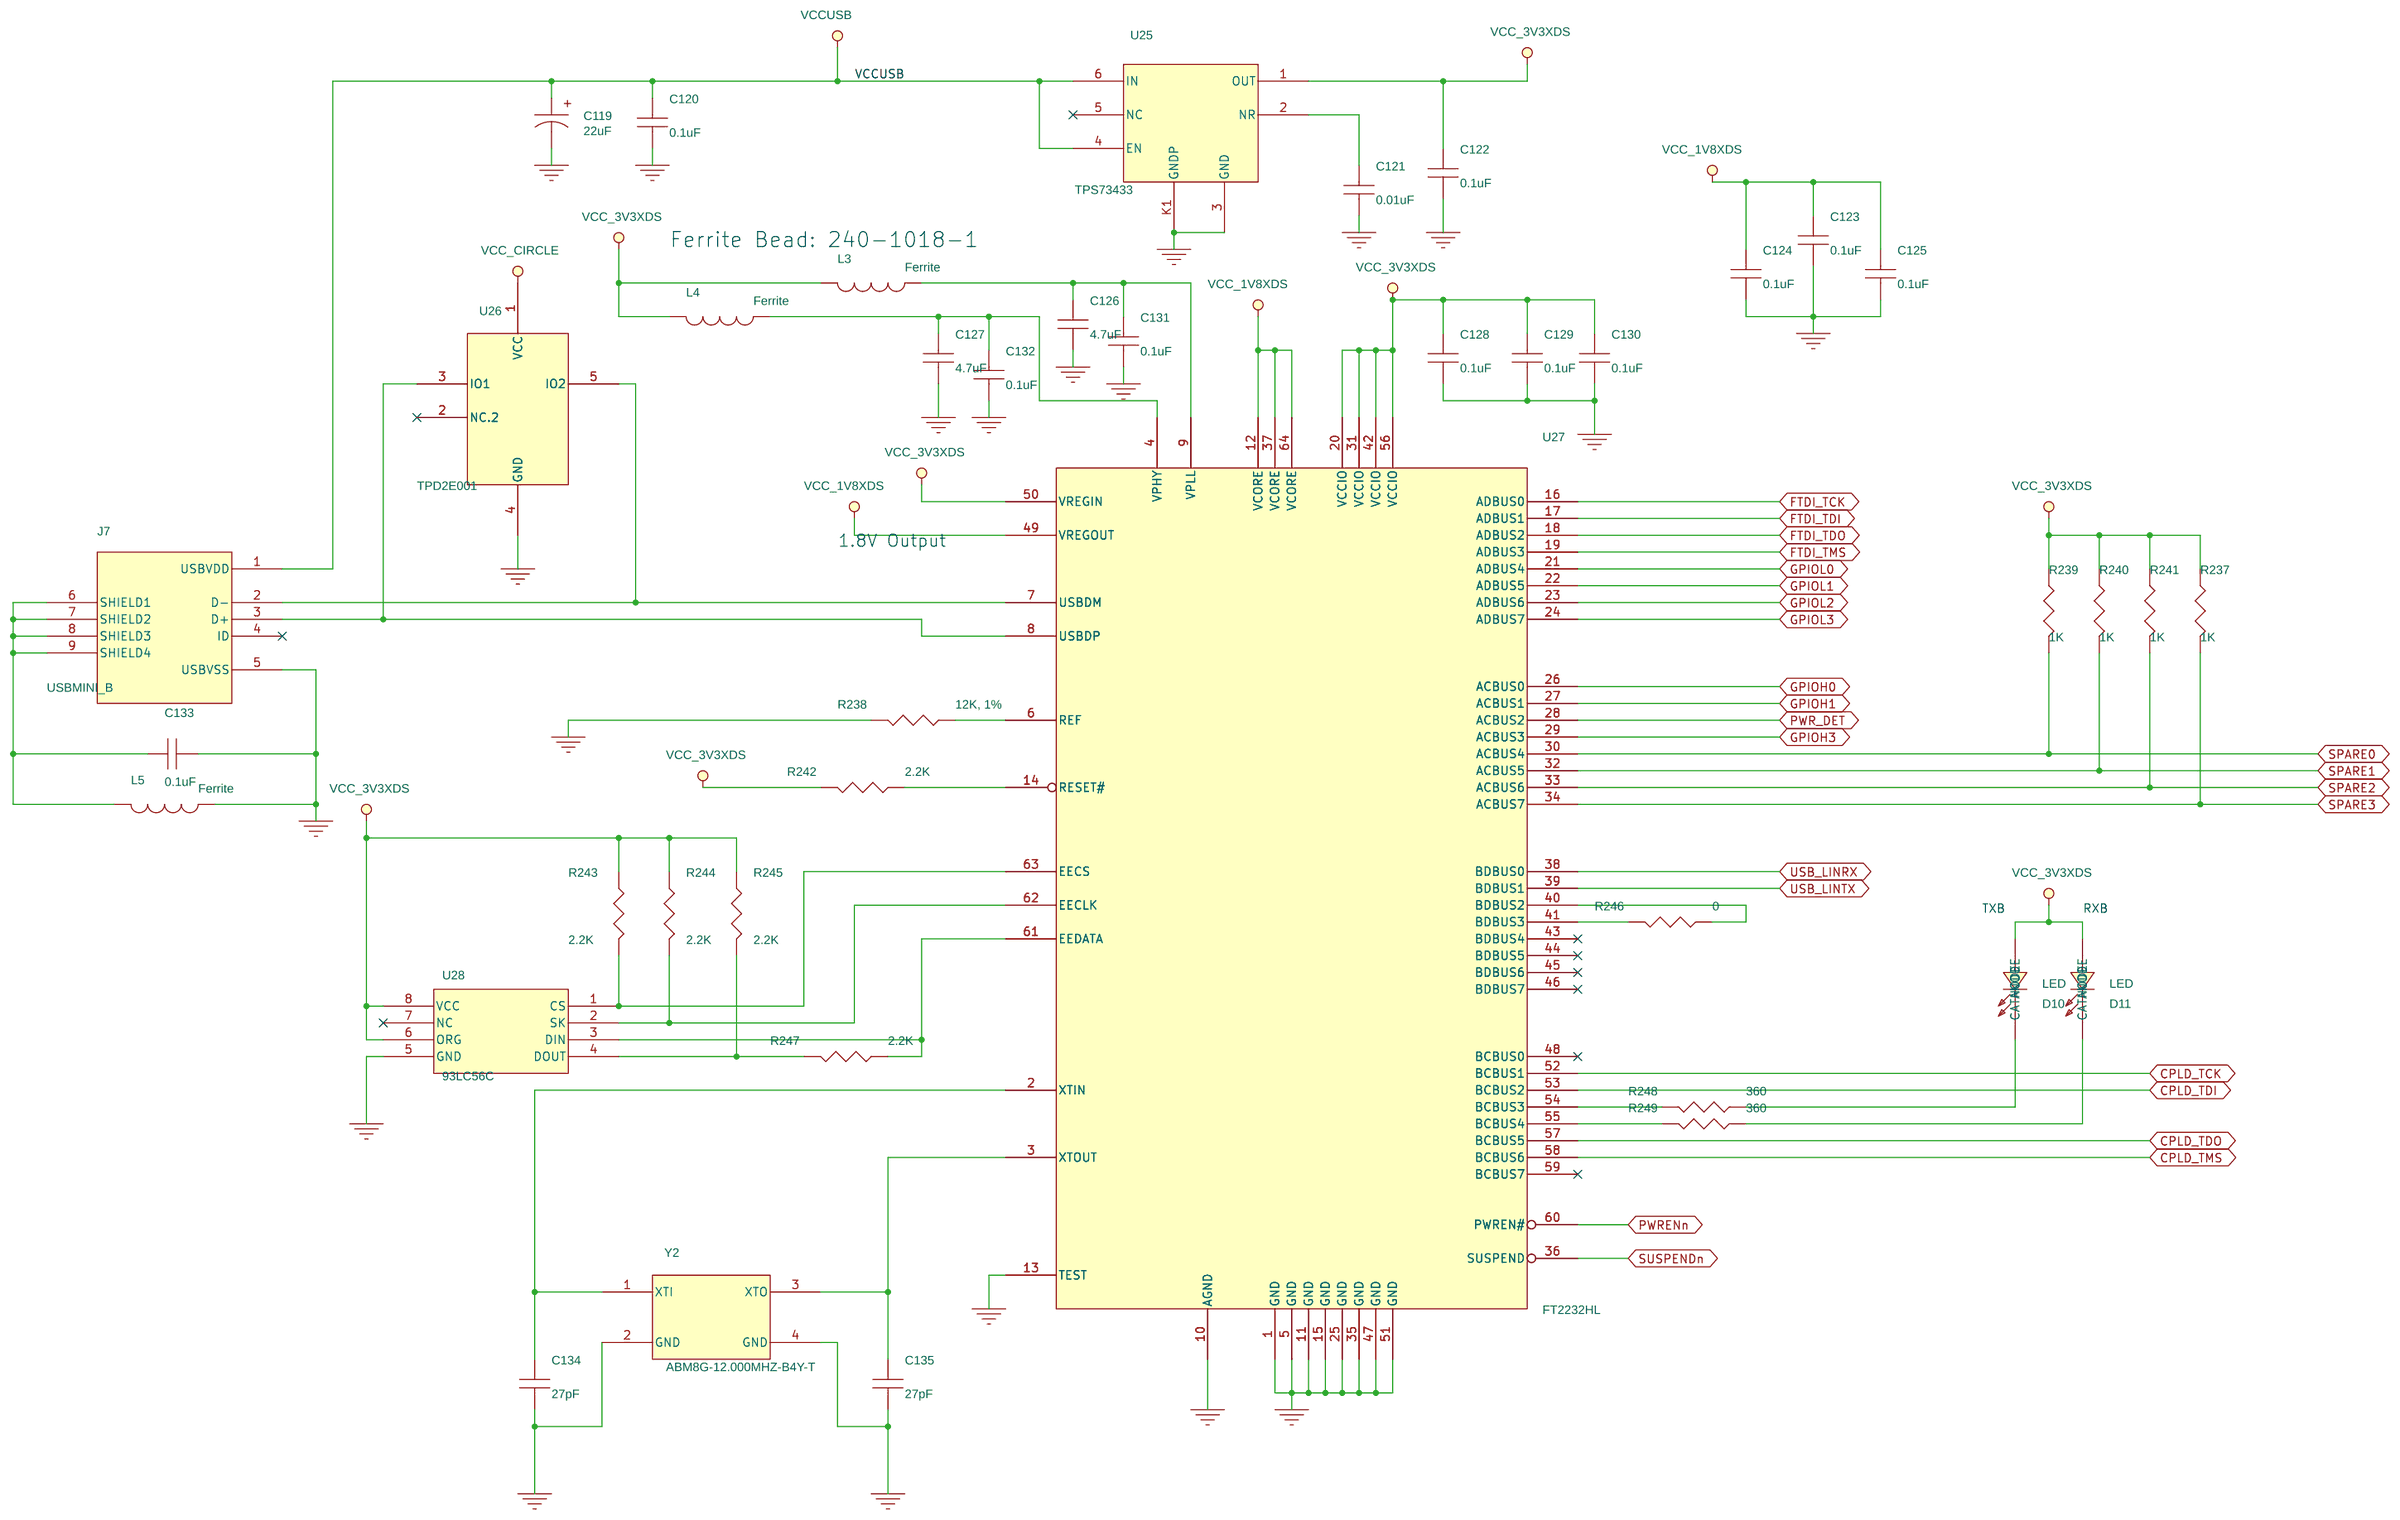
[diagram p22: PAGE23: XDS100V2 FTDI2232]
24 PAGE11: FET SW FOR 1st USB: size B; note: FET SWs FOR 1st USB HOST
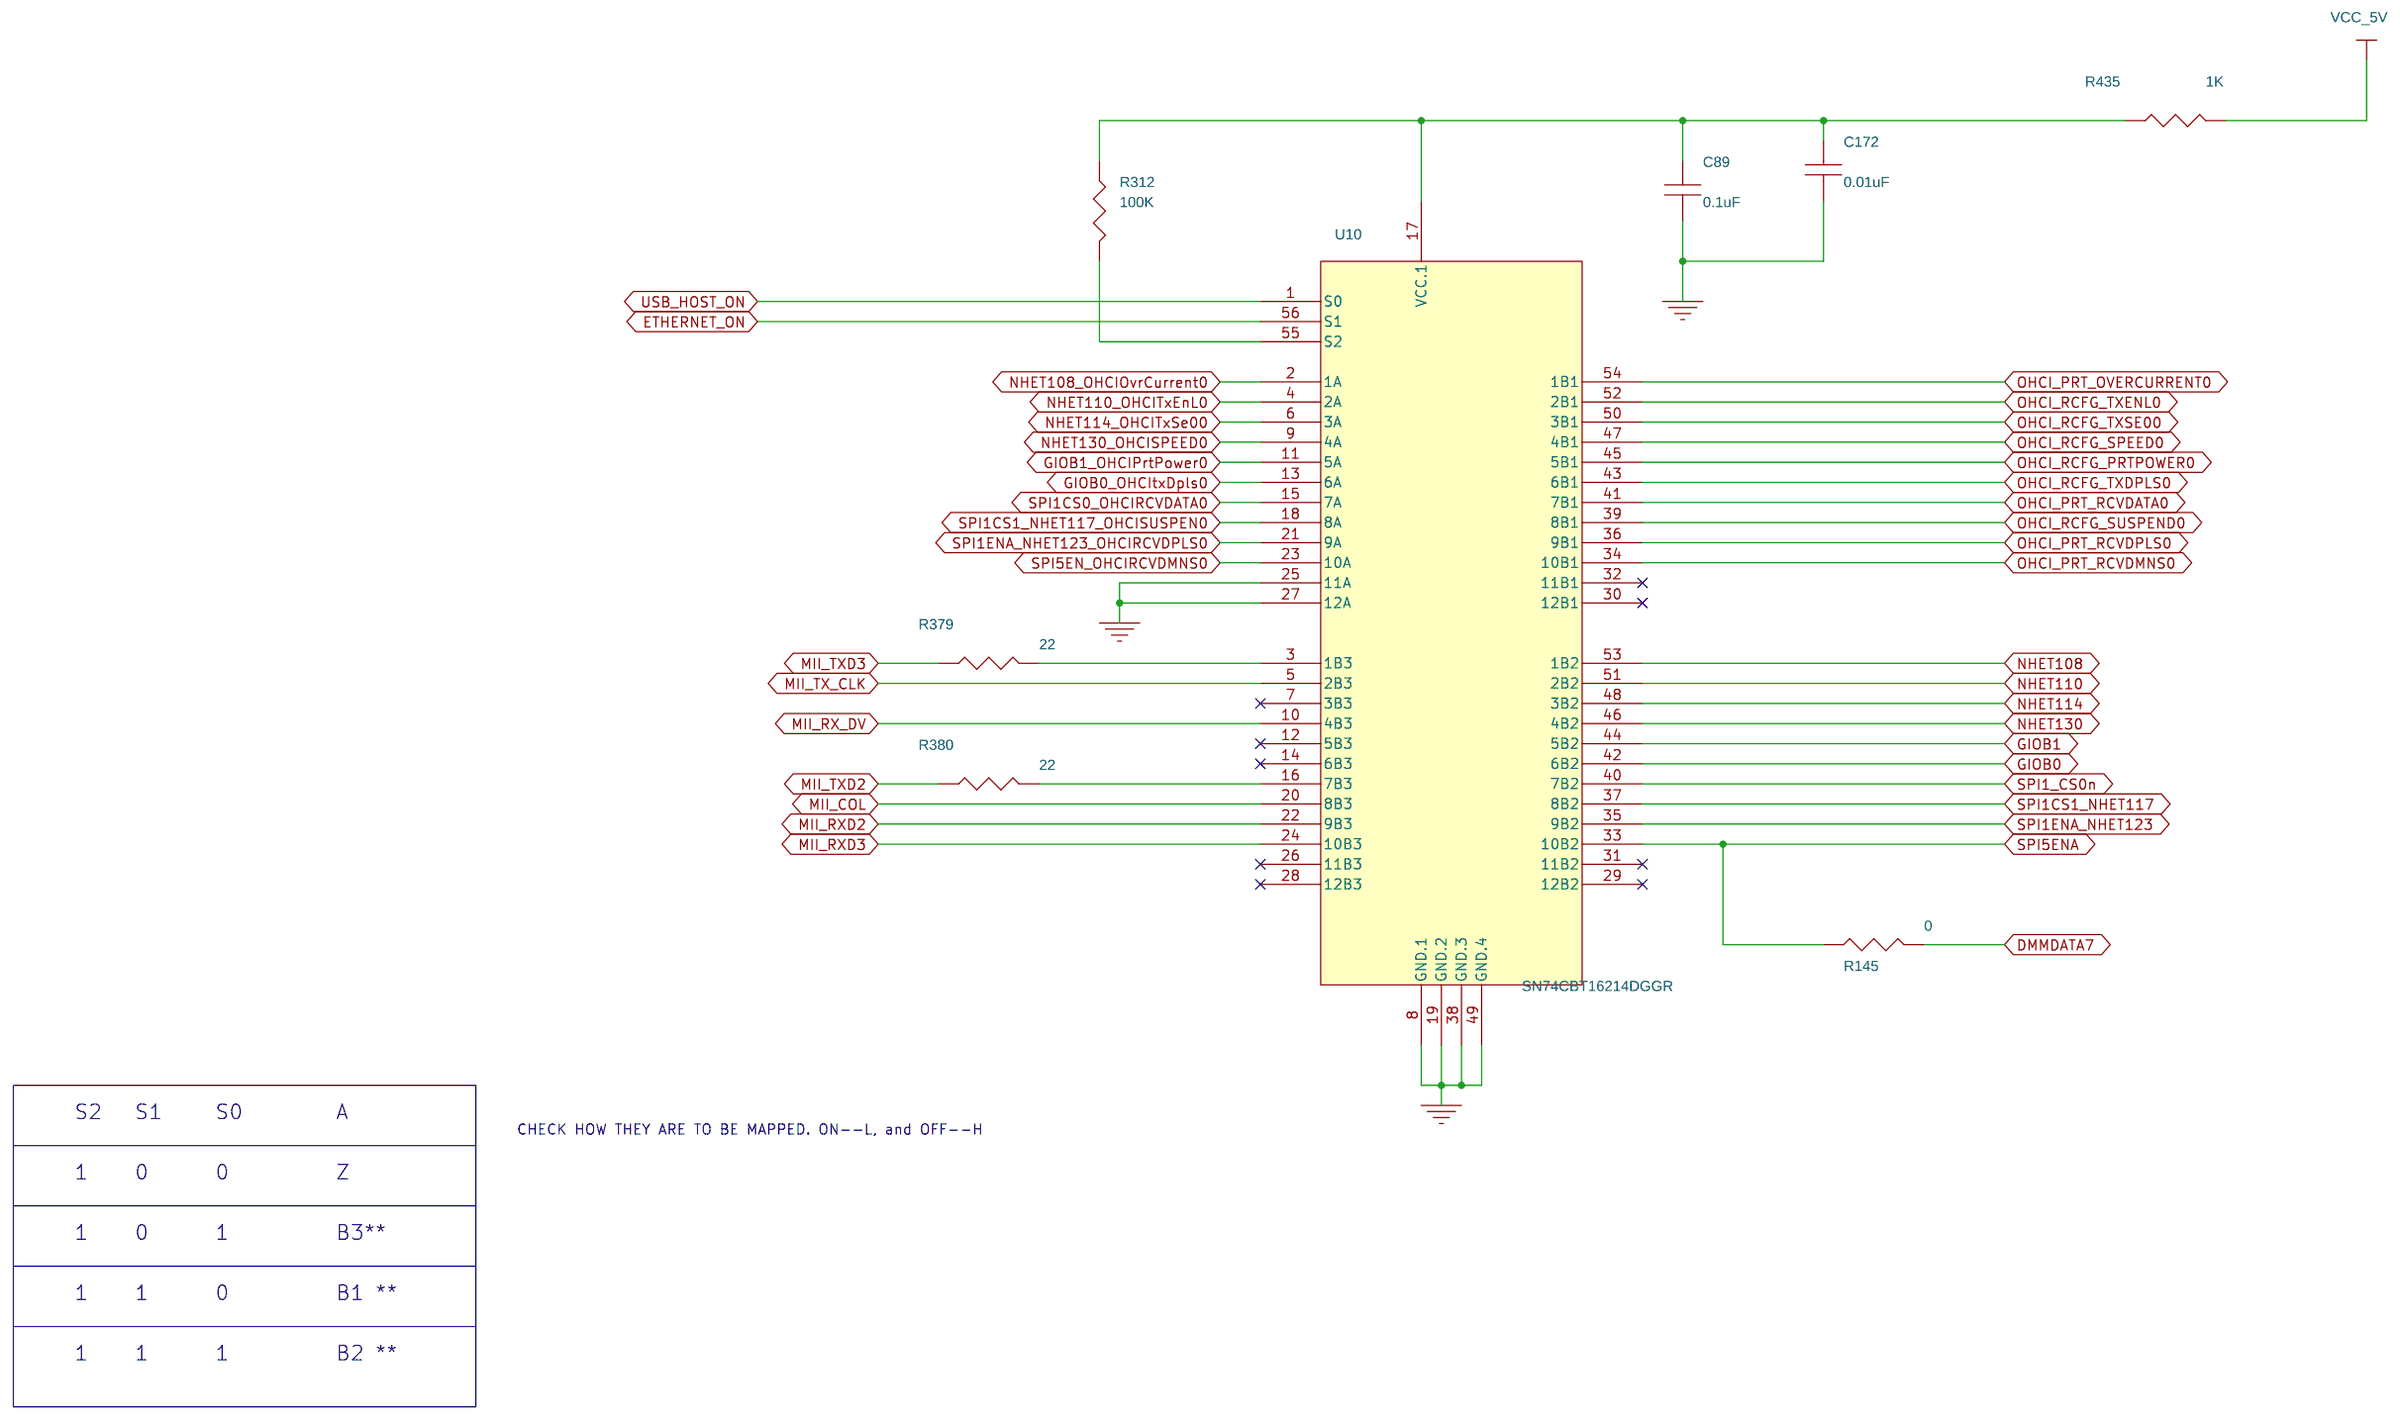
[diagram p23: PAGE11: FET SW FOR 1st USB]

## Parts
sheet PAGE05: MCU ETM & RSVED_RTP
R38  22  [r0402]
R42  22  [r0402]
R45  22  [r0402]
R46  22  [r0402]
R51  10K  [r0402]
R53  10K  [r0402]
R121  0  [r0402]
TP1  TestPoint1  [tp1-6040]
U1  TMS570LC43x  [BGA337]  (sections A,B,C,D,E,F,G,H,I)
sheet PAGE07: MCU JTAG & OSC
C27  10pF  [c0402]
C28  10pF  [c0402]
C29  22pF  [c0603]
C30  0.1uF  [c0402]
C31  0.1uF  [c0402]
C178  1uF  [c0402]
D1  RED  [d0603]
D2  BLUE  [d0603]
L1  Ferrite  [L0805]
Q2  IRLML6346  [SOT23]
R126  10k  [r0402]
R127  10k  [r0402]
R128  10k  [r0402]
R129  0  [r0402]
R130  0  [r0402]
R131  1k  [r0402]
R132  100  [r0402]
R133  0  [r0402]
R134  0  [r0402]
R135  2.2K  [r0402]
R136  NOP  [r0402]
R137  0  [r0402]
R138  100  [r0402]
R139  500  [r0402]
R225  22  [r0402]
R226  22  [r0402]
R257  22  [r0402]
R310  4.7K  [r0402]
R313  NOP  [r0402]
R314  10K  [r0402]
T1  IRLML6302  [SOT23]
TP2  TestPoint1  [tp1-6040]
TP3  TestPoint1  [tp1-6040]
U2  SN74LVC1G07DCK  [SC70-5]
Y1  16 MHz  [SMD2]
Y3  ASEM1-25.000MHZ-LC-T  [ASEM-SMT4]
sheet PAGE10: MCU Power & GND
C32  0.1uF  [c0402]
C33  0.1uF  [c0402]
C34  22uF  [c1210_pol]
C35  0.1uF  [c0402]
C36  0.1uF  [c0402]
C37  0.1uF  [c0402]
C38  0.1uF  [c0402]
C39  0.1uF  [c0402]
C40  0.1uF  [c0402]
C41  22uF  [c0805]
C42  0.1uF  [c0402]
C43  0.1uF  [c0402]
C44  0.1uF  [c0402]
C45  22uF  [c1210_pol]
C46  0.1uF  [c0402]
C47  22uF  [c0805]
C48  0.1uF  [c0402]
C49  0.1uF  [c0402]
C50  0.1uF  [c0402]
C51  0.1uF  [c0402]
C52  0.1uF  [c0402]
C53  0.1uF  [c0402]
C54  0.1uF  [c0402]
C55  0.1uF  [c0402]
C56  0.1uF  [c0402]
C57  0.01uF  [c0402]
C58  22uF  [c1210_pol]
C59  0.1uF  [c0402]
C60  0.1uF  [c0402]
C61  0.1uF  [c0402]
C62  0.1uF  [c0402]
C63  0.1uF  [c0402]
C64  0.1uF  [c0402]
C65  0.1uF  [c0402]
C66  22uF  [c0805]
C67  0.1uF  [c0402]
C68  22uF  [c1210_pol]
C69  0.1uF  [c0402]
C70  0.1uF  [c0402]
E1  NFM21PC474R1C3D  [NFM21P]
R140  0.02  [r2512]
R141  0.02  [r2512]
R142  0.02  [r2512]
R143  0.02  [r2512]
R144  0.02  [r2512]
TP4  TestPoint1  [tp1-6040]
TP5  TestPoint1  [tp1-6040]
TP6  TestPoint1  [tp1-6040]
TP7  TestPoint1  [tp1-6040]
TP14  TestPoint1  [tp1-6040]
TP15  TestPoint1  [tp1-6040]
TP16  TestPoint1  [tp1-6040]
TP17  TestPoint1  [tp1-6040]
TP18  TestPoint1  [tp1-6040]
TP19  TestPoint1  [tp1-6040]
TP20  TestPoint1  [tp1-6040]
TP21  TestPoint1  [tp1-6040]
TP22  TestPoint1  [tp1-6040]
TP23  TestPoint1  [tp1-6040]
sheet PAGE11: FET SW FOR 1st USB
C89  0.1uF  [c0402]
C172  0.01uF  [c0402]
R145  0  [r0402]
R312  100K  [r0402]
R379  22  [r0402]
R380  22  [r0402]
R435  1K  [r0402]
U10  SN74CBT16214DGGR  [TSSOP56]
sheet PAGE16: USB 1st OHCI Host
C90  0.1uF  [c0402]
C91  0.1uF  [c0402]
C92  0.1uF  [c0402]
C93  0.1uF  [c0402]
J18  USBCONN_A  [USB-A]
R159  100K  [r0402]
R160  20K  [r0402]
R161  22  [r0402]
R162  22  [r0402]
R163  15K  [r0402]
R164  15K  [r0402]
R165  1M  [r0402]
R363  22  [r0402]
R364  22  [r0402]
R365  22  [r0402]
U12  TPS2552DBV  [SOT-23-6]
U13  TUSB1105RGT  [QFN-RGT]
sheet PAGE20: CAN Transceivers
C111  4.7nF  [c0402]
C112  0.1uF  [c0402]
C113  0.1uF  [c0402]
C114  4.7nF  [c0402]
C115  0.1uF  [c0402]
C116  0.1uF  [c0402]
J2  CON3  [11mmx7mm]
J3  CON3  [11mmx7mm]
R211  NOP  [r0402]
R212  10k  [r0402]
R213  62  [r0402]
R214  62  [r0402]
R215  NOP  [r0402]
R216  10K  [r0402]
R217  62  [r0402]
R218  62  [r0402]
U21  SN65HVDA541  [8SOIC]
U22  SN65HVDA541  [8SOIC]
sheet PAGE21: JTAG & MIPI Conn
C117  NOP  [c0402]
C118  0.1uF  [c0402]
DS1  JTAG_DIS  [d0603]
J4  ARM20PIN_JTAG  [10x2]
J19  ETM-MIPI  [30x2]
R219  0  [r0402]
R220  10k  [r0402]
R221  22  [r0402]
R222  22  [r0402]
R223  22  [r0402]
R224  22  [r0402]
R227  22  [r0402]
R228  NOP  [r0402]
R229  NOP  [r0402]
R230  NOP  [r0402]
R231  NOP  [r0402]
R232  NOP  [r0402]
R233  NOP  [r0402]
R234  10k  [r0402]
R235  0  [r0402]
R236  220  [r0402]
U24  SN74AHC1G14  [SC70-5]
sheet PAGE23: XDS100V2 FTDI2232
C119  22uF  [c1210_pol]
C120  0.1uF  [c0402]
C121  0.01uF  [c0402]
C122  0.1uF  [c0402]
C123  0.1uF  [c0402]
C124  0.1uF  [c0402]
C125  0.1uF  [c0402]
C126  4.7uF  [c0402]
C127  4.7uF  [c0402]
C128  0.1uF  [c0402]
C129  0.1uF  [c0402]
C130  0.1uF  [c0402]
C131  0.1uF  [c0402]
C132  0.1uF  [c0402]
C133  0.1uF  [c0402]
C134  27pF  [c0402]
C135  27pF  [c0402]
D10  LED  [d0603]
D11  LED  [d0603]
J7  USBMINI_B  [USB-MiniB]
L3  Ferrite  [L0805]
L4  Ferrite  [L0805]
L5  Ferrite  [L0805]
R237  1K  [r0402]
R238  12K, 1%  [r0603]
R239  1K  [r0402]
R240  1K  [r0402]
R241  1K  [r0402]
R242  2.2K  [r0402]
R243  2.2K  [r0402]
R244  2.2K  [r0402]
R245  2.2K  [r0402]
R246  0  [r0402]
R247  2.2K  [r0402]
R248  360  [r0402]
R249  360  [r0402]
U25  TPS73433  [TI_SON6-PWP]
U26  TPD2E001  [SOT5]
U27  FT2232HL  [64LQFP]
U28  93LC56C  [8SOIC]
Y2  ABM8G-12.000MHZ-B4Y-T  [ABM8G-SMT4]
sheet PAGE24: XDS100V2 CPLD
C136  0.1uF  [c0402]
C137  0.1uF  [c0402]
C138  0.1uF  [c0402]
D12  LED  [d0603]
D18  DIODE SCHOTTKY  [d1005_pol]
D19  DIODE SCHOTTKY  [d1005_pol]
R250  360  [r0402]
R251  22  [r0402]
R252  22  [r0402]
R253  22  [r0402]
R254  22  [r0402]
R255  22  [r0402]
R260  22  [r0402]
R261  360  [r0402]
R262  22  [r0402]
R263  22  [r0402]
R264  5.1K  [r0402]
R265  120K  [r0402]
R266  120K  [r0402]
R267  120K  [r0402]
TP9  TestPoint1  [tp1-6040]
TP10  TestPoint1  [tp1-6040]
U29  XC2C32A_CPG56  [CFG56]
U30  LMV341IDCKR  [DCK_SC70]
sheet PAGE27: Power Input
C157  22uF,50V  [c7343_pol]
C158  0.01uF  [c0402]
C159  1uF  [c0402]
C160  10pF  [c0603]
C161  4700pF  [c0603]
C162  0.1uF  [c0402]
C163  22uF,25V  [c7343_pol]
C164  0.1uF  [c0402]
C165  220uF  [c0402]
C166  22uF,25V  [c7343_pol]
C167  0.1uF  [c0805]
C168  10uF  [c1206_pol]
C169  10uF  [c1206_pol]
C170  1uF  [c0603]
C171  10nF  [c0402]
D13  SMCJ18A  [SMC-DO-214AB]
D14  MURS120T3  [SMB]
DS5  12V  [d0603]
F1  2A_QuickBlow  [F1812]
L6  BLM41P750SPT  [L1806]
L7  BLM41P750SPT  [L1806]
L8  BLM41P750SPT  [L1806]
L9  10 uH  [NR10050]
L10  BLM41P750SPT  [L1806]
P1  DC8  [100438]
R302  10K  [r0603]
R303  5.90K, 1%  [r0603]
R304  NOP  [r0402]
R305  7.5K, 1%  [r0603]
R306  4.64K, 1%  [r0603]
R307  1K, 1%  [r0603]
R308  1K  [r0402]
TP11  TestPoint1  [tp1-6040]
TP12  TestPoint1  [tp1-6040]
U37  TPS54350PWP  [PSOP16T]
U39  TPS73733QDRBRQ1  [DRB_SON8]
sheet PAGE28: EXP P1 and EXP P2
J9  EXP_P1  [MMS_2mmx33]
J10  EXP_P2  [MMS_2mmx33]

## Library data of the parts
R38 R42 R45 R46 R161 R162 R363-R365 R379 R380 = R_0: Manufacturer: Panasonic - ECG; Part Number: ERJ-2GEJ220X
R51 R53 R126-R128 R304 = R: Manufacturer: Panasonic - ECG; Part Number: ERJ-2GEJ103X
R121 R219 R246 = R: Manufacturer: Panasonic - ECG; Part Number: ERJ-2GE0R00X
TP1-TP7 TP9-TP12 TP14-TP23 = TestPoint1
U1 = TMS570LS30336U_BGA337_19: Manufacturer: TI; PACKAGE: 1; Part Number: TMS570LS3x
C27 C28 = CAP_NP: Manufacturer: Panasonic - ECG; Part Number: UMK105CG100DV-F
C29 = CAP_NP_1: Manufacurer: AVX Corporation; Part Number: 06033A220JAT2A
C30-C33 C35-C40 C42-C44 C46 C48-C56 C59-C65 C67 C69 C70 C89-C93 C112 C113 C115-C118 C120 C122-C125 C128-C133 C136-C138 C162 C164 = CAP_NP: Manufacturer: Panasonic - ECG; Part Number: EMK105BJ104KV-F
C159 C178 = CAP_NP: Manufacturer: Panasonic - ECG; Part Number: ECJ-0EB1A105M
D1 = LED_0_v2: Manufacturer: Panasonic - SSG; Part Number: LNJ212R8ARA
D2 = LED_0_v2: Manufacurer: Panasonic - SSG; Part Number: LNJ926W8CRA
L1 L3 L4 = INDUCTOR: FERRITE 500MA 600 OHM 0805 SMD; Manufacturer: Laird-Signal Integrity Products; Part Number: HZ0805E601R-10
Q2 = 2N6766_1: Manufacturer: International Rectifier; Part Number: IRLML6346TRPBF
R129 R130 R145 = RESISTOR: Manufacturer: Panasonic - ECG; Part Number: ERJ-2GE0R00X
R131 R139 R308 = RESISTOR: Manufacturer: Panasonic - ECG; Part Number: ERJ-2GEJ102X
R132 R138 = R: Manufacturer: Panasonic - ECG; Part Number: ERJ-2GEJ101X
R133 R134 R136 R137 = R_2: Manufacturer: Panasonic - ECG; Part Number: ERJ-2GE0R00X
R135 R242-R245 R247 = R: Manufacturer: Panasonic - ECG; Part Number: ERJ-2RKF2201X
R221-R227 R257 = RESISTOR_1: Part Number: ERJ-2GEJ220X
R310 R314 = R_0: Manufacturer: Panasonic - ECG; Part Number: ERJ-2GEJ103X
R237 R239-R241 R313 = R: Manufacturer: Panasonic - ECG; Part Number: ERJ-2GEJ102X
T1 = 2N6756_0: Manufacturer: International Rectifier; Part Number: IRLML6302TRPBF
U2 = SN74LVC1G07DCK: Part Number: SN74LVC1G07DCKR
Y1 = CRYSTAL: Manufacturer: TXC CORPORATION; Part Number: 7A-16.000MAAJ-T
Y3 = CB3LV-3C-25M0000: Manufacturer: Abracon Corporation
C34 C45 C58 C68 C119 = Cap_22uF_Tan_6_1.3V_20%_EIA_B: Part Number: TAJB226K006RNJ
C41 C47 C66 = CAP_NP: Manufacturer: Panasonic - ECG; Part Number: JMK212BJ226MG-T
C57 C121 C158 C172 = CAP_NP: Manufacturer: Panasonic - ECG; Part Number: ECJ-0EB1C103K
E1 = NFM21PC474R1C3D
R140-R144 = RESISTOR: Manufacturer: Panasonic - ECG; Part Number: ERJ-M1WSF20MU
R312 = R: Manufacturer: Panasonic - ECG; Part Number: ERJ-2GEJ104X
R435 = R: Part Number: ERJ-2GEJ102X
U10 = SN74CBT16214DGGR
J18 = USBCONN_A: Manufacturer: FCI; Part Number: 73725-0110BLF
R159 = R_0: Manufacturer: Panasonic - ECG; Part Number: ERJ-2GEJ104X
R160 = R_0: Manufacturer: Panasonic - ECG; Part Number: ERJ-2GEJ203X
R163 R164 = R_0: Manufacturer: Panasonic - ECG; Part Number: ERJ-2GEJ153X
R165 = R: Manufacturer: Panasonic - ECG; Part Number: ERJ-2GEJ105X
U12 = TPS2552DBV
U13 = TUSB1105RGT: Part Number: TUSB1105RGTR
C111 C114 = CAP_NP: Manufacturer: Vishay; Part Number: VJ0402Y472KXJCW1BC
J2 J3 = CON3: Manufacturer: On Shore Technology Inc; Part Number: OSTTE030161
R211 = R: Part Number: ERJ-2RKF2201X
R212 R215 R216 R220 R234 = R: Part Number: ERJ-2GEJ103X
R213 R214 R217 R218 = R: Manufacturer: Panasonic - ECG; Part Number: ERJ-2GEJ620X
U21 U22 = SN65HVDA540: Manufacturer: TI; Part Number: SN65HVDA541QDR
D12 DS1 DS5 = LED_0: Manufacturer: Panasonic - SSG; Part Number: LNJ926W8CRA
J4 = ARM20PIN_JTAG_0: Part Number: TSM-110-01-T-DV-ND
J19 = ETM-MIPI_0: Manufacturer: Samtec Inc; Part Number: QSH-030-01-L-D-A
R228-R233 = RESISTOR_1
R235 = R_0: Part Number: ERJ-2GE0R00X
R236 = R: Resistor, 5%, 1/10W; Part Number: ERJ-2GEJ221X
U24 = SN74AHC1G14: Manufacturer: TI; Part Number: SN74AHC1G14DCKR
C126 C127 = CAP_NP: Manufacturer: Murata Electronics North America; Part Number: GRM155R60J475ME87D
C134 C135 = CAP_NP: Manufacturer: Panasonic - ECG; Part Number: ECJ-0EC1H270J
D10 D11 = LED_0: Manufacturer: LNJ926W8CRA; Part Number: LNJ926W8CRA
J7 = USBMINI_B_0: Manufacturer: JAE Electronics; Part Number: DX2R005HN2E700
L5 = INDUCTOR: FERRITE 500MA 600 OHM 0805 SMD; Manufacturer: Murata Electronics North America; Part Number: BLM21PG221SN1D
R238 = R: Manufacturer: Panasonic - ECG; Part Number: ERJ-3EKF1202V
R248-R250 R261 = R: Manufacturer: Panasonic - ECG; Part Number: ERJ-2GEJ361X
U25 = TPS71718: Part Number: TPS73433DRV
U26 = TPDE0001RSE_0: Part Number: TPD2E001DRLR
U27 = FT2232HQ_3: Manufacturer: FTDICHIPS
U28 = 93C46: Manufacturer: ISSI; Part Number: 93LC56C-I/SN
Y2 = ESC-120-20-30B: Manufacturer: Abracon Corporation
D18 D19 = DIODE_SCHOTTKY: Part Number: CDBF0130L
R251-R255 R260 R262 = R: Manufacturer: Panasonic - ECG; Part Number: ERJ-2GEJ220X
R263 = R: Part Number: ERJ-2GEJ220X
R264 = R: Manufacturer: Panasonic - ECG; Part Number: ERJ-2GEJ512X
R265-R267 = R: Manufacturer: Panasonic - ECG; Part Number: ERJ-2GEJ124X
U29 = XC2C32A_CP56: Part Number: XC2C32A-6CPG56C
U30 = LMV341IDCKR
C157 C166 = CAP_P: Part Number: T491D226M025AT
C160 = CAP_NP: Manufacturer: Panasonic - ECG; Part Number: C1608C0G1H100D
C161 = CAP_NP: Manufacturer: Panasonic - ECG; Part Number: CC0603KRX7R9BB472
C163 C165 = CAP_P
C167 = CAP_NP: Part Number: CC0805KRX7R9BB104
C168 C169 = CAP_P: Manufacturer: Kemet; Part Number: T491A106M020AT
C170 = Cap_0.1uF_Cermc_16V_10%_402: Manufacturer: Panasonic - ECG; Part Number: JMK107BJ105KK-T
C171 = Cap_0.1uF_Cermc_16V_10%_402: Manufacturer: Panasonic - ECG; Part Number: C1005X7R1C103M
D13 = SMCJ6_0.0A: Manufacturer: Littelfuse Inc
D14 = DIODE_0
F1 = F_2.5A: POLYSWITCH RESET 1.5A 24V SMD TR; Manufacturer: TE Connectivity; Part Number: MINISMDC150F/24-2
L6 L7 L10 = FERRITE_CHIP: Manufacturer: Steward; Part Number: HI1806N910R-10; Spectrum Part#: 101126-0001
L8 = FERRITE_CHIP: Part Number: HI1806N910R-10
L9 = INDUCTOR_IRON: Manufacturer: Taiyo Yuden; Part Number: NR10050T100M
P1 = DC8_0: CONN POWER JACK 2.1MM; Manufacturer: CUI Inc; Part Number: CP-002A-ND
R302 = RESISTOR: Part Number: ERJ-3GEYJ103V
R303 = RESISTOR: Manufacturer: Panasonic - ECG; Part Number: ERJ-3EKF5901V
R305 = RESISTOR: Manufacturer: Panasonic - ECG; Part Number: ERJ-3EKF7501V
R306 = RESISTOR: Manufacturer: Panasonic - ECG; Part Number: ERJ-3EKF4641V
R307 = RESISTOR: Part Number: ERJ-3EKF1001V
U37 = TPS54350PWP_4: Manufacturer: TI
U39 = TPS73701DRB
J9 J10 = HEADER_33x2: Manufacturer: Samtec Inc; Part Number: MMS-133-01-T-DV

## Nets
GND: C29.2 C30.2 C31.2 C32.2 C33.2 C34.2 C35.2 C36.2 C37.2 C38.2 C39.2 C40.2 C41.2 C42.2 C43.2 C44.2 C45.2 C46.2 C47.2 C48.2 C49.2 C50.2 C51.2 C52.2 C53.2 C54.2 C55.2 C56.2 C57.2 C58.2 C59.2 C60.2 C61.2 C62.2 C63.2 C64.2 C65.2 C66.2 C67.2 C68.2 C69.2 C70.2 C89.2 C90.2 C91.2 C92.2 C93.1 C111.2 C112.2 C113.2 C114.2 C115.2 C116.2 C117.2 C118.2 C119.2 C120.2 C121.2 C122.2 C123.2 C124.2 C125.2 C126.2 C127.2 C128.2 C129.2 C130.2 C131.2 C132.2 C133.2 C134.2 C135.2 C136.2 C137.2 C138.2 C157.2(CATHODE) C159.2 C163.2(CATHODE) C164.2 C165.2(CATHODE) C166.2(CATHODE) C167.2 C168.2(CATHODE) C169.2(CATHODE) C170.1 C171.1 C172.2 C178.1 D2.2 D13.2(Anode) D14.ANODE DS1.2(CATHODE) DS5.2(CATHODE) E1.2 J2.2 J3.2 J4.4(GND1) J4.6(GND2) J4.10(GND4) J4.12(GND5) J4.14(GND6) J4.16(GND7) J4.18(GND8) J4.20(GND9) J7.5(USBVSS) J9.2 J9.4 J9.13 J9.14 J9.29 J9.30 J9.39 J9.40 J9.49 J9.50 J9.59 J9.66 J10.2 J10.29 J10.30 J10.39 J10.40 J10.57 J10.58 J10.66 J18.4(GND) J19.15(GND2) J19.16(GND1) J19.58(GND3) J19.61(MH1) J19.62(MH2) J19.63(MH3) J19.64(MH4) L5.1 P1.2(SLEEVE) P1.3(SHUNT) R129.2 R133.2 R160.2 R163.2 R164.2 R165.1 R212.2 R216.2 R238.1 R266.1 R267.1 R304.1 R307.2 R313.2 TP4.1 TP5.1 TP6.1 TP7.1 U1.A1(GND) U1.A2(GND) U1.A18(GND) U1.A19(GND) U1.B1(GND) U1.B19(GND) U1.H8(GND) U1.H9(GND) U1.H11(GND) U1.H12(GND) U1.J8(GND) U1.J9(GND) U1.J10(GND) U1.J11(GND) U1.J12(GND) U1.K9(GND) U1.K10(GND) U1.K11(GND) U1.L8(GND) U1.L9(GND) U1.L10(GND) U1.L11(GND) U1.L12(GND) U1.M8(GND) U1.M9(GND) U1.M11(GND) U1.M12(GND) U1.V1(GND) U1.V19(VSSAD) U1.W1(GND) U1.W2(GND) U1.W16(VSSAD) U1.W18(VSSAD) U1.W19(VSSAD) U2.3(GND) U10.8(GND.1) U10.19(GND.2) U10.25(11A) U10.27(12A) U10.38(GND.3) U10.49(GND.4) U12.2(GND) U13.6(MODE) U13.17(PAD) U21.2(GND) U22.2(GND) U24.3(GND) U25.3(GND) U25.K1(GNDP) U26.4(GND) U27.1(GND) U27.5(GND) U27.10(AGND) U27.11(GND) U27.13(TEST) U27.15(GND) U27.25(GND) U27.35(GND) U27.47(GND) U27.51(GND) U28.5(GND) U29.C7(GND) U29.F8(GND) U29.H4(GND) U30.2(GND) U37.10(AGND) U37.11(PGND1) U37.17(POWERPAD) U39.4(GND) U39.9(PAD) Y2.2(GND) Y2.4(GND) Y3.2(GND) ; also on sheet 2 3 5 6 9 10 11 25 27 28 29
VCC_1V2: C34.1 C58.1 E1.1 R140.1 TP14.1 ; also on sheet 5 10
VCC_1V8XDS: C123.1 C124.1 C125.1 C137.1 D19.1(ANODE) U27.12(VCORE) U27.37(VCORE) U27.49(VREGOUT) U27.64(VCORE) U29.G8(VCC18)
VCC_3V3: C30.1 C45.1 C68.1 C91.1 C92.1 C112.1 C116.1 C118.1 C168.1(ANODE) C170.2 D18.1(ANODE) J4.2(VSupply) J19.1(VCC1_3.3V) J19.12(VCC2_3.3V) L1.2 R51.2 R53.2 R126.1 R127.1 R128.1 R131.2 R135.2 R141.1 R143.1 R219.2 R220.2 R234.2 R264.2 R310.2 R314.2 T1.2(SOURCE) TP16.1 TP21.1 U2.5(Vcc) U13.7(VCC_IO) U13.13(VREG_3.3) U13.14(VCC_5) U21.5(VIO) U22.5(VIO) U24.5(VCC) U39.1(OUT) ; also on sheet 3 5 7 8 9 10 25 27 28 29
VCC_3V3XDS: C122.1 C128.1 C129.1 C130.1 C136.1 D10.1(ANODE) D11.1(ANODE) L3.2 L4.2 R237.2 R239.2 R240.2 R241.2 R242.1 R243.2 R244.2 R245.2 R250.1 R265.2 U25.1(OUT) U27.20(VCCIO) U27.31(VCCIO) U27.42(VCCIO) U27.50(VREGIN) U27.56(VCCIO) U28.6(ORG) U28.8(VCC) U29.D3(VCCAUX) U29.H6(VCCIO1) U30.6(V+)
VCC_5V: C113.1 C115.1 C166.1(ANODE) C169.1(ANODE) L10.2 R159.1 R211.1 R215.1 R308.1 R435.2 TP12.1 U12.1(IN) U21.3(VCC) U22.3(VCC) U39.8(IN) ; also on sheet 10 27
VCC_12V: C157.1(ANODE) C167.1 F1.2(P2) L6.1 L7.1 L8.1 R302.1 ; also on sheet 10
VCC_ADC: R144.1 TP23.1 ; also on sheet 6 10
VCCUSB: C119.1 C120.1 J7.1(USBVDD) U25.4(EN) U25.6(IN) U26.1(VCC)
2MCU_TRSTn: J19.8(nTRST) R221.1 R233.2 R257.1
AD1EVT: J9.63 ; also on sheet 29
AD1IN0: J9.32 ; also on sheet 6
AD1IN1: J9.31 ; also on sheet 6
AD1IN2: J9.34 ; also on sheet 6
AD1IN3: J9.33 ; also on sheet 6
AD1IN4: J9.36 ; also on sheet 6
AD1IN5: J9.35 ; also on sheet 6
AD1IN6: J9.38 ; also on sheet 6
AD1IN7: J9.37 ; also on sheet 6
AD1IN8: J9.52 ; also on sheet 6 9
AD1IN9: J9.51 ; also on sheet 6 9
AD1IN10: J9.54 ; also on sheet 6
AD1IN11: J9.53 ; also on sheet 6
AD1IN12: J9.56 ; also on sheet 6
AD1IN13: J9.55 ; also on sheet 6
AD1IN14: J9.58 ; also on sheet 6
AD1IN15: J9.57 ; also on sheet 6
AD2IN0: J9.42 ; also on sheet 6
AD2IN1: J9.41 ; also on sheet 6
AD2IN2: J9.44 ; also on sheet 6
AD2IN3: J9.43 ; also on sheet 6
AD2IN4: J9.46 ; also on sheet 6
AD2IN5: J9.45 ; also on sheet 6
AD2IN6: J9.48 ; also on sheet 6
AD2IN7: J9.47 ; also on sheet 6
ADREFHI: J9.61 ; also on sheet 6
ADREFLO: J9.62 ; also on sheet 6
ARM_JTAG_RESETn: R227.1 ; also on sheet 5
CAN1_RX: U21.4(RXD) ; also on sheet 2 26
CAN1_TX: U21.1(TXD) ; also on sheet 2 26
CAN2_RX: U22.4(RXD) ; also on sheet 2 26
CAN2_TX: U22.1(TXD) ; also on sheet 2 26
CORE_VCC: C32.1 C33.1 C35.1 C36.1 C37.1 C38.1 C39.1 C40.1 C41.1 C42.1 C43.1 C44.1 R140.2 TP15.1 U1.F9(CORE_VCC) U1.F10(CORE_VCC) U1.H10(CORE_VCC) U1.K6(CORE_VCC) U1.K8(CORE_VCC) U1.K12(CORE_VCC) U1.K14(CORE_VCC) U1.L6(CORE_VCC) U1.M10(CORE_VCC) U1.P10(CORE_VCC)
CPLD_TCK: U27.52(BCBUS1) U29.K10(TCK)
CPLD_TDI: U27.53(BCBUS2) U29.J10(TDI)
CPLD_TDO: U27.57(BCBUS5) U29.A6(TDO)
CPLD_TMS: U27.58(BCBUS6) U29.K9(TMS)
DMMDATA2: J9.20 ; also on sheet 7 11
DMMDATA3: J9.19 ; also on sheet 7 11
DMMDATA7: R145.2 ; also on sheet 11
ECLK: J10.3 R130.2
EMIFA0_NHET201: J10.28 ; also on sheet 3 8
EMIFA1_NHET203: J10.27 ; also on sheet 3 8
EMIFA2_ETMD11: J10.26 J19.41(TRACEDAT11) ; also on sheet 3 8
EMIFA2_ETMD11B: U1.E6(ETM_DATA[[11]/EMIF__ADDR[2]) ; also on sheet 8
EMIFA3_ETMD10: J10.25 J19.39(TRACEDAT10) ; also on sheet 3 8
EMIFA3_ETMD10B: U1.E7(ETM_DATA[[10]/EMIF__ADDR[3]) ; also on sheet 8
EMIFA4_ETMD9: J10.24 J19.37(TRACEDAT9) ; also on sheet 3 8
EMIFA4_ETMD9B: U1.E8(ETM_DATA[[09]/EMIF__ADDR[4]) ; also on sheet 8
EMIFA5_ETMD8: J10.23 J19.35(TRACEDAT8) ; also on sheet 3 8
EMIFA5_ETMD8B: U1.E9(ETM_DATA[[08]/EMIF__ADDR[5]) ; also on sheet 8
EMIFA6_RTPD13: J10.22 ; also on sheet 3 8 11
EMIFA7_RTPD12: J10.21 ; also on sheet 3 8 11
EMIFA8_RTPD11: J10.20 ; also on sheet 3 8 11
EMIFA9_RTPD10: J10.19 ; also on sheet 3 8 11
EMIFA10_RTPD9: J10.18 ; also on sheet 3 8 11
EMIFA11_RTPD8: J10.17 ; also on sheet 3 8 11
EMIFA12_RTPD6: J10.16 ; also on sheet 3 8 11
EMIFA13_RTPD5: J10.15 ; also on sheet 8 11
EMIFA14_RTPD4: J10.14 ; also on sheet 8 11
EMIFA15_RTPD3: J10.13 ; also on sheet 8 11
EMIFA16_RTPD2: J10.12 ; also on sheet 8 11
EMIFA17_RTPD1: J10.11 ; also on sheet 8 11
EMIFA18_RTPD0: J10.10 ; also on sheet 8 11
EMIFA19_RTPNENA: J10.9 ; also on sheet 8 11
EMIFA20_RTPNSYNC: J10.8 ; also on sheet 8 11
EMIFA21_RTPCLK: J10.7 ; also on sheet 8 11
EMIFBA0_ETMD12: J10.37 J19.43(TRACEDAT12) R38.1 R51.1 ; also on sheet 3
EMIFBA1_NHET205: J10.35 ; also on sheet 3 8
EMIFD0_ETMD16: J10.42 J19.51(TRACEDAT16) U1.K15(ETM_DATA[[16]/EMIF__DATA[[0]) ; also on sheet 3
EMIFD1_ETMD17: J10.41 J19.53(TRACEDAT17) U1.L15(ETM_DATA[[17]/EMIF__DATA[[1]) ; also on sheet 3
EMIFD2_ETMD18: J10.44 J19.55(TRACEDAT18) U1.M15(ETM_DATA[[18]/EMIF__DATA[[2]) ; also on sheet 3
EMIFD3_ETMD19: J10.43 J19.18(TRACEDAT19) U1.N15(ETM_DATA[[19]/EMIF__DATA[[3]) ; also on sheet 3
EMIFD4_ETMD20: J10.46 J19.20(TRACEDAT20) U1.E5(ETM_DATA[[20]/EMIF__DATA[[4]) ; also on sheet 3
EMIFD5_ETMD21: J10.45 J19.22(TRACEDAT21) U1.F5(ETM_DATA[[21]/EMIF__DATA[[5]) ; also on sheet 3
EMIFD6_ETMD22: J10.48 J19.24(TRACEDAT22) U1.G5(ETM_DATA[[22]/EMIF__DATA[[6]) ; also on sheet 3
EMIFD7_ETMD23: J10.47 J19.26(TRACEDAT23) U1.K5(ETM_DATA[[23]/EMIF__DATA[[7]) ; also on sheet 3
EMIFD8_ETMD24: J10.50 J19.28(TRACEDAT24) U1.L5(ETM_DATA[[24]/EMIF__DATA[[8]) ; also on sheet 3
EMIFD9_ETMD25: J10.49 J19.30(TRACEDAT25) U1.M5(ETM_DATA[[25]/EMIF__DATA[[9]) ; also on sheet 3
EMIFD10_ETMD26: J10.52 J19.32(TRACEDAT26) U1.N5(ETM_DATA[[26]/EMIF__DATA[[10]) ; also on sheet 3
EMIFD11_ETMD27: J10.51 J19.34(TRACEDAT27) U1.P5(ETM_DATA[[27]/EMIF__DATA[[11]) ; also on sheet 3
EMIFD12_ETMD28: J10.54 J19.36(TRACEDAT28) U1.R5(ETM_DATA[[28]/EMIF__DATA[[12]) ; also on sheet 3
EMIFD13_ETMD29: J10.53 J19.38(TRACEDAT29) U1.R6(ETM_DATA[[29]/EMIF__DATA[[13]) ; also on sheet 3
EMIFD14_ETMD30: J10.56 J19.40(TRACEDAT30) U1.R7(ETM_DATA[[30]/EMIF__DATA[[14]) ; also on sheet 3
EMIFD15_ETMD31: J10.55 J19.42(TRACEDAT31) U1.R8(ETM_DATA[[31]/EMIF__DATA[[15]) ; also on sheet 3
EMIFNCS2: J10.34 ; also on sheet 8
EMIFNCS3_RTPD14: J10.32 ; also on sheet 8 11
EMIFNCS4_RTPD7: J10.6 ; also on sheet 8 11
EMIFNDQM0_ETMD15: J10.38 J19.49(TRACEDAT15) R45.1 ; also on sheet 3
EMIFNDQM1_ETMD14: J10.36 J19.47(TRACEDAT14) R46.1 ; also on sheet 3
EMIFNOE_ETMD13: J10.33 J19.45(TRACEDAT13) R42.1 R53.1
EMIFNWE_EMIFNWR: J10.31 ; also on sheet 3 8
ETH_RESETn: J10.5 R134.2 R261.2 U1.B17(nRST) ; also on sheet 5 28
ETHERNET_ON: U10.56(S1) ; also on sheet 29
ETMDATA0: J19.19(TRACEDAT0) U1.R12(ETMDATA[0])
ETMDATA1: J19.21(TRACEDAT1) U1.R13(ETMDATA[1])
ETMDATA2: J19.23(TRACEDAT2) U1.J15(ETMDATA[2])
ETMDATA3: J19.25(TRACEDAT3) U1.H15(ETMDATA[3])
ETMDATA4: J19.27(TRACEDAT4) U1.G15(ETMDATA[4])
ETMDATA5: J19.29(TRACEDAT5) U1.F15(ETMDATA[5])
ETMDATA6: J19.31(TRACEDAT6) U1.E15(ETMDATA[6])
ETMDATA7: J19.33(TRACEDAT7) U1.E14(ETMDATA[7])
ETMTRACECLKOUT: J19.13(TRACECLKOUT) U1.R10(ETMTRACECLKOUT)
ETMTRACECTL: J19.17(TRACECTL) U1.R11(ETMTRACECTL)
EXP_12V: J9.1 J9.3 J9.65 J10.1 J10.65 L6.2 L7.2 ; also on sheet 2
EXP_EMIF_nWAIT: J10.60 ; also on sheet 8
FLTP1: TP2.1 U1.J5(FLTP1)
FLTP2: TP3.1 U1.H5(FLTP2)
FTDI_TCK: U27.16(ADBUS0) U29.H10(IO12_14)
FTDI_TDI: U27.17(ADBUS1) U29.K8(IO12_13)
FTDI_TDO: U27.18(ADBUS2) U29.H8(IO12_12)
FTDI_TMS: U27.19(ADBUS3) U29.H5(IO12_11)
GIOB0: U10.42(6B2) ; also on sheet 2
GIOB0_OHCItxDpls0: U10.13(6A) ; also on sheet 12
GIOB1: U10.44(5B2) ; also on sheet 2
GIOB1_OHCIPrtPower0: U10.11(5A) ; also on sheet 12
GPIOH0: U27.26(ACBUS0) U29.K1(IO12_6)
GPIOH1: U27.27(ACBUS1) U29.J1(IO12_5)
GPIOH3: U27.29(ACBUS3) U29.F3(IO12_2)
GPIOL0: U27.21(ADBUS4) U29.K5(IO12_10)
GPIOL1: U27.22(ADBUS5) U29.H3(IO12_9)
GPIOL2: U27.23(ADBUS6) U29.K3(IO12_8)
GPIOL3: U27.24(ADBUS7) U29.K2(IO12_7)
IO_VCC: C46.1 C47.1 C48.1 C49.1 C50.1 C51.1 C52.1 C53.1 C54.1 C55.1 C59.1 C60.1 C61.1 C62.1 C63.1 C64.1 C65.1 C66.1 C67.1 R141.2 TP17.1 U1.F6(IO_VCC) U1.F7(IO_VCC) U1.F11(IO_VCC) U1.F12(IO_VCC) U1.F13(IO_VCC) U1.F14(IO_VCC) U1.G6(IO_VCC) U1.G14(IO_VCC) U1.H6(IO_VCC) U1.H14(IO_VCC) U1.J6(IO_VCC) U1.L14(IO_VCC) U1.M6(IO_VCC) U1.M14(IO_VCC) U1.N6(IO_VCC) U1.N14(IO_VCC) U1.P6(IO_VCC) U1.P7(IO_VCC) U1.P8(IO_VCC) U1.P9(IO_VCC) U1.P12(IO_VCC) U1.P13(IO_VCC) U1.P14(IO_VCC)
JTAG_SELn: C117.1 J4.8(GND3) R220.1 R235.2 U24.2(I)
KGD: C27.2 C28.1 U1.L2(KELVIN-GND)
MCU_RTCK: J4.11(RTCK) J19.7(RTCLK) R225.1 R229.2 R262.2
MCU_TCK: J19.3(TCK) R128.2 R132.1 R224.1 R230.2 R260.2 U1.B18(TCK)
MCU_TDI: J19.5(TDI) R127.2 R222.1 R232.2 R253.2 T1.1(GATE) U1.A17(TDI)
MCU_TDO: J4.13(TDO) J19.4(TDO) R226.1 R228.2 R255.2
MCU_TMS: J19.2(TMS) R126.2 R223.1 R231.2 R251.2 U1.C19(TMS)
MII_COL: U10.20(8B3) ; also on sheet 28
MII_RX_DV: U10.10(4B3) ; also on sheet 28
MII_RXD2: U10.22(9B3) ; also on sheet 28
MII_RXD3: U10.24(10B3) ; also on sheet 28
MII_TX_CLK: U10.5(2B3) ; also on sheet 28
MII_TXD2: R380.1 ; also on sheet 28
MII_TXD3: R379.1 ; also on sheet 28
MIPI_JTAG_RESETn: J19.6(nRSESET) R234.1 ; also on sheet 5
nERROR: D1.2 J10.4 U1.B14(nERROR)
NHET108: U10.53(1B2) ; also on sheet 2
NHET108_OHCIOvrCurrent0: U10.2(1A) ; also on sheet 1
NHET110: U10.51(2B2) ; also on sheet 2
NHET110_OHCITxEnL0: U10.4(2A) ; also on sheet 1
NHET114: U10.48(3B2) ; also on sheet 2
NHET114_OHCITxSe00: U10.6(3A) ; also on sheet 1
NHET130: U10.46(4B2) ; also on sheet 2
NHET130_OHCISPEED0: U10.9(4A) ; also on sheet 1
OHCI_PRT_OVERCURRENT0: R159.2 U10.54(1B1) U12.4(nFAULT)
OHCI_PRT_RCVDATA0: R364.1 U10.41(7B1)
OHCI_PRT_RCVDMNS0: R365.1 U10.34(10B1)
OHCI_PRT_RCVDPLS0: R363.1 U10.36(9B1)
OHCI_RCFG_PRTPOWER0: U10.45(5B1) U12.3(EN)
OHCI_RCFG_SPEED0: U10.47(4B1) U13.8(SPEED)
OHCI_RCFG_SUSPEND0: U10.39(8B1) U13.5(SUSPEND)
OHCI_RCFG_TXDPLS0: U10.43(6B1) U13.11(VPO/VO)
OHCI_RCFG_TXENL0: U10.52(2B1) U13.1(OE)
OHCI_RCFG_TXSE00: U10.50(3B1) U13.12(VMO/FSE0)
OSCIN: C27.1 U1.K1(OSCIN) Y1.1
OSCOUT: C28.2 U1.L1(OSCOUT) Y1.2
POR_RESETn: J9.60 R139.1 U1.W7(nPORRST) ; also on sheet 5
PWGOOD: R263.2 U30.4(OUT)
PWR_DET: U27.28(ACBUS2) U29.H1(IO12_3)
PWRENn: D12.2(CATHODE) U27.60(PWREN#) U29.G3(IO12_4)
RMII_MHZ_50: R137.1 ; also on sheet 28
RMII_REFCLK: R136.1 ; also on sheet 29
RSTn: R314.1 U2.4(Y) ; also on sheet 2
RTP_RTCK: R229.1 ; also on sheet 11
RTP_TCK: R230.1 ; also on sheet 11
RTP_TDI: R232.1 ; also on sheet 11
RTP_TDO: R228.1 ; also on sheet 11
RTP_TMS: R231.1 ; also on sheet 11
RTP_TRSTn: R233.1 ; also on sheet 11
SHDNn: U29.G10(IO12_15) U30.5(SHDNn)
SPARE0: R239.1 U27.30(ACBUS4) U29.F1(IO21_1)
SPARE1: R240.1 U27.32(ACBUS5) U29.E3(IO21_2)
SPARE2: R241.1 U27.33(ACBUS6) U29.E1(IO21_3)
SPARE3: R237.1 U27.34(ACBUS7) U29.D1(IO21_4)
SPI1_CLK: J9.6 ; also on sheet 7
SPI1_CS0n: J9.8 U10.40(7B2)
SPI1CS0_OHCIRCVDATA0: U10.15(7A) ; also on sheet 7
SPI1CS1_NHET117: J9.7 U10.37(8B2)
SPI1CS1_NHET117_OHCISUSPEN0: U10.18(8A) ; also on sheet 7
SPI1CS2_NHET119: J9.10 ; also on sheet 29
SPI1CS3_NHET121: J9.9 ; also on sheet 7
SPI1ENA_NHET123: J9.5 U10.35(9B2)
SPI1ENA_NHET123_OHCIRCVDPLS0: U10.21(9A) ; also on sheet 7
SPI1SIMO: J9.11 ; also on sheet 7
SPI1SOMI: J9.12 ; also on sheet 7
SPI2CLK: J10.64 ; also on sheet 7 9
SPI2CS0: J10.63 ; also on sheet 7 9
SPI2ENA: J10.62 ; also on sheet 7 9
SPI2SIMO: J10.61 ; also on sheet 7 9
SPI2SOMI: J10.59 ; also on sheet 7 9
SPI3CS0_AD2EVT_GIOB2: J9.64 ; also on sheet 2 7
SPI5CLK: J9.16 ; also on sheet 29
SPI5CS0n: J9.18 ; also on sheet 7
SPI5CS1n: J9.17 ; also on sheet 7
SPI5EN_OHCIRCVDMNS0: U10.23(10A) ; also on sheet 7
SPI5ENA: J9.15 R145.1 U10.33(10B2)
SPI5SIMO0: J9.21 ; also on sheet 29
SPI5SIMO1: J9.23 ; also on sheet 7
SPI5SIMO2: J9.25 ; also on sheet 7
SPI5SIMO3: J9.27 ; also on sheet 7
SPI5SOMI0: J9.22 ; also on sheet 29
SPI5SOMI1: J9.24 ; also on sheet 7
SPI5SOMI2: J9.26 ; also on sheet 7
SPI5SOMI3: J9.28 ; also on sheet 7
SUSPENDn: U27.36(SUSPEND) U29.G1(IO12_1)
T_DIS: R236.1 R254.2 U24.4(O)
TEST: R129.1 U1.U2(TEST)
USB_HOST_ON: U10.1(S0) ; also on sheet 29
USB_LINRX: U27.38(BDBUS0) ; also on sheet 26
USB_LINTX: U27.39(BDBUS1) ; also on sheet 26
XDS100_TRSTn: Q2.2(SOURCE) R252.2 R313.1 U1.D18(nTRST)
N16377739: J18.2(D-) R161.1 R164.1
N16377807: R161.2 U13.9(D-)
N16377811: R162.2 U13.10(D+)
N16378765: J18.3(D+) R162.1 R163.1
N16379682: R160.1 U12.5(ILIM)
N16447101: C134.1 U27.2(XTIN) Y2.1(XTI)
N16447133: C135.1 U27.3(XTOUT) Y2.3(XTO)
N16447193: R244.1 U27.62(EECLK) U28.2(SK)
N16447197: R247.2 U27.61(EEDATA) U28.3(DIN)
N16447213: R243.1 U27.63(EECS) U28.1(CS)
N16447237: R245.1 R247.1 U28.4(DOUT)
N16447249: C133.1 J7.6(SHIELD1) J7.7(SHIELD2) J7.8(SHIELD3) J7.9(SHIELD4) L5.2
N16447313: J7.2(D-) U26.5(IO2) U27.7(USBDM)
N16447347: J7.3(D+) U26.3(IO1) U27.8(USBDP)
N16448035: C121.1 U25.2(NR)
N16448183: R246.2 U27.40(BDBUS2)
N16448319: R246.1 U27.41(BDBUS3)
N16448353: D11.2(CATHODE) R249.2
N16448503: D10.2(CATHODE) R248.2
N16448773: C127.1 C132.1 L4.1 U27.4(VPHY)
N16448793: C126.1 C131.1 L3.1 U27.9(VPLL)
N16452517: DS1.1(ANODE) R236.2
N16458309: R215.2 R216.1 U22.8(STB)
N16458325: J3.1 R217.1 U22.7(CANH)
N16458377: J3.3 R218.2 U22.6(CANL)
N16458397: C114.1 R217.2 R218.1
N16459257: R211.2 R212.1 U21.8(STB)
N16459281: J2.1 R213.1 U21.7(CANH)
N16459297: J2.3 R214.2 U21.6(CANL)
N16459313: C111.1 R213.2 R214.1
N16579445: C56.1 C57.1 R142.2 TP19.1 U1.J14(VCCPLL2) U1.P11(VCCPLL1)
N16583392: C69.1 R143.2 TP20.1 U1.F8(VCCP)
N16680082: C29.1 R132.2
N16681462: D1.1 R131.1
N16742796: C90.1 J18.1(VBUS) U12.6(OUT)
N16759617: J19.57(GND4) R235.1
N16792011: R262.1 U29.D10(I_2)
N16792033: TP10.1 U29.E8(IO21_16)
N16792037: TP9.1 U29.C10(IO21_15)
N16792041: R261.1 U29.B10(IO21_14)
N16792045: R260.1 U29.A10(IO21_13) U29.C5(IO21_11) U29.C8(IO21_12)
N16792105: R251.1 U29.A3(IO21_6) U29.C1(IO21_5)
N16792115: R252.1 U29.A2(IO21_7)
N16792117: R253.1 U29.B1(IO21_8)
N16792119: R254.1 U29.A1(IO21_9)
N16792121: R255.1 U29.C4(IO21_10)
N16792172: R263.1 U29.F10(IO12_16)
N16792244: C138.1 R264.1 R266.2 U30.1(IN+)
N16908135: J4.1(VTRef) R219.1
N16908259: J4.3(TRSTn) R221.2
N16908262: J4.5(TDI) R222.2
N16908265: J4.7(TMS) R223.2
N16908268: J4.9(TCK) R224.2
N16908277: J4.15(SRSTn) R227.2
N16943003: R121.1 U1.R9(ETMTRACECLKIN/EXTCLKIN2)
N16949985: C31.1 L1.1 Y3.4(VCC)
N16949989: R135.1 Y3.1(OE)
N16963211: R136.2 R137.2 Y3.3(OUT)
N16984426: R265.1 R267.2 U30.3(IN-)
N17055021: R130.1 U1.A12(ECLK)
N17119320: C70.1 R144.2 TP22.1 U1.W15(VCCAD)
N17139095: C93.2 J18.5(SHLD1) J18.6(SHLD2) J18.7(SHLD3) J18.8(SHLD4) R165.2
N17228864: D12.1(ANODE) R250.2
N17237828: R238.2 U27.6(REF)
N17239229: R242.2 U27.14(RESET#)
N17240395: R249.1 U27.55(BCBUS4)
N17240398: R248.1 U27.54(BCBUS3)
N17412986: D2.1 R138.2
N17412988: R138.1 T1.3(DRAIN)
N17416675: R134.1 U2.2(A)
N17823516: D13.1(Cathode) F1.1(P1) P1.1(CENTER)
N17825916: R308.2 U39.5(EN)
N17877464: DS5.1(ANODE) R302.2
N17877514: C161.2 C164.1 C165.1(ANODE) L9.2 L10.1 R306.2
N17877545: C162.2 D14.CATHODE L9.1 U37.14(PH1) U37.15(PH2)
N17877547: C163.1(ANODE) L8.2 U37.1(VIN1) U37.2(VIN2)
N17877557: C162.1 U37.16(BOOT)
N17877565: C160.2 R303.2 R305.1 R306.1 R307.1 U37.9(VSENSE)
N17877571: C158.1 C160.1 U37.8(COMP)
N17877579: C159.1 U37.12(VBIAS)
N17877585: TP11.1 U37.4(PWRGD)
N17877616: C161.1 R305.2
N17877644: R304.2 U37.5(RT)
N17898338: R133.1 U1.V4(RESERVED20)
N18167119: C89.1 C172.1 R312.1 R435.1 U10.17(VCC.1)
N18167490: R312.2 U10.55(S2)
N18170112: D18.2(CATHODE) D19.2(CATHODE) U29.C6(VCCIO2)
N18238282: E1.3 R142.1 TP18.1
N18278991: R365.2 U13.4(VM)
N18278994: R363.2 U13.3(VP)
N18278997: R364.2 U13.2(RCV)
N18279542: R379.2 U10.3(1B3)
N18279551: R380.2 U10.16(7B3)
N18327011: C158.2 R303.1
N18330060: C171.2 U39.3(NR/FB)
N18487230: R38.2 U1.E13(ETM_DATA[[12]/EMIF__BA[0])
N18487233: R42.2 U1.E12(ETM_DATA[[13]/EMIF__nOE)
N18487236: R46.2 U1.E11(ETM_DATA[[14]/EMIF__nDQM[1])
N18487239: R45.2 U1.E10(ETM_DATA[[15]/EMIF__nDQM[0])
N18546301: R121.2 TP1.1
N18567417: R225.2 U1.A16(RTCK)
N18567438: R226.2 U1.C18(TDO)
N18612587: Q2.3(DRAIN) R257.2 R310.1
N18620465: C178.2 Q2.1(GATE) R139.2

Not connected (* = marked no-connect by the designer): J4 17(DBGREQ)* 19(DBGACK)*; J7 4(ID)*; J19 9(NC12)* 10(NC13)* 11(NC11)* 14(NC14)* 44(NC1)* 46(NC2)* 48(NC3)* 50(NC4)* 52(NC5)* 54(NC6)* 56(NC7)* 59(NC9)* 60(NC8)*; U1 N18(NC1)* P15(NC4)* P16(NC3)* P17(NC2)* R1(NC9)* R14(NC6)* R15(NC5)* T2(RESERVED16)* T3(RESERVED15)* T4(RESERVED12)* T9(RESERVED5)* T10(RESERVED3)* T11(RESERVED17)* T13(NC8)* T14(NC7)* U3(RESERVED14)* U4(RESERVED11)* U5(RESERVED10)* U6(RESERVED9)* U7(RESERVED8)* U8(RESERVED7)* U9(RESERVED6)* U10(RESERVED4)* U11(RESERVED2)* U12(RESERVED19)* V3(RESERVED13)* V11(RESERVED1)* W4(NC10)* W11(RESERVED18)*; U2 1(NC)*; U10 7(3B3)* 12(5B3)* 14(6B3)* 26(11B3)* 28(12B3)* 29(12B2)* 30(12B1)* 31(11B2)* 32(11B1)*; U13 15(VPU_3.3)* 16(SOFTCON)*; U24 1*; U25 5(NC)*; U26 2(NC.2)*; U27 43(BDBUS4)* 44(BDBUS5)* 45(BDBUS6)* 46(BDBUS7)* 48(BCBUS0)* 59(BCBUS7)*; U28 7(NC)*; U29 A4(NC11)* A5(NC9)* A7(NC6)* A8(NC10)* A9(NC7)* C3(NC12)* D8(NC8)* E10(NC5)* H7(NC4)* K4(NC1)* K6(NC2)* K7(NC3)*; U37 3(UVLO)* 6(SYNC)* 7(ENA)* 13(LSG)*; U39 2(NC1)* 6(NC2)* 7(NC3)*

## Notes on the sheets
sheet 13
- +5V VOLTAGE REGULATOR
- 12V Input
- Connect at pin 10
- 5V @ 3Amp Max
- 3.3 sq in AGND,
  min thermal pad
sheet 14
- To MCU
- TO PHY
- When using RMII, the OSC will be 50MHz
- place R225, R226,
  R132, and C29 close to
  U1
- nTRST from Emulator
- nEEROR
- nTRST to Device
sheet 15
- EMU0
- EMU1
- This is JTAG
  PD power. We
  pull PD to
  VCC_3V3
sheet 16
- 10 bypass caps for CPU_CORE_VCC
- 16 bypas caps for IO_VCC_3V3
- 4 GND test points at the board's 4 corners
sheet 17
- FULL SIZE A CONNECTOR
sheet 18
- MIPI
  Connector
  QSH-030-01
- JTAG_SELn = HIGH  --> XDS100
- JTAG_SELn = LOW  --> ARM
  JTAG and MIPI
sheet 21
- changed all the name to Gladiator only
sheet 23
- Ferrite Bead: 240-1018-1
- 1.8V Output
- TXB
- RXB
sheet 24
- S2
- S1
- S0
- A
- CHECK HOW THEY ARE TO BE MAPPED. ON--L, and OFF--H
- 1
- 0
- 0
- Z
- 1
- 0
- 1
- B3**
- 1
- 1
- 0
- B1 **
- 1
- 1
- 1
- B2 **
